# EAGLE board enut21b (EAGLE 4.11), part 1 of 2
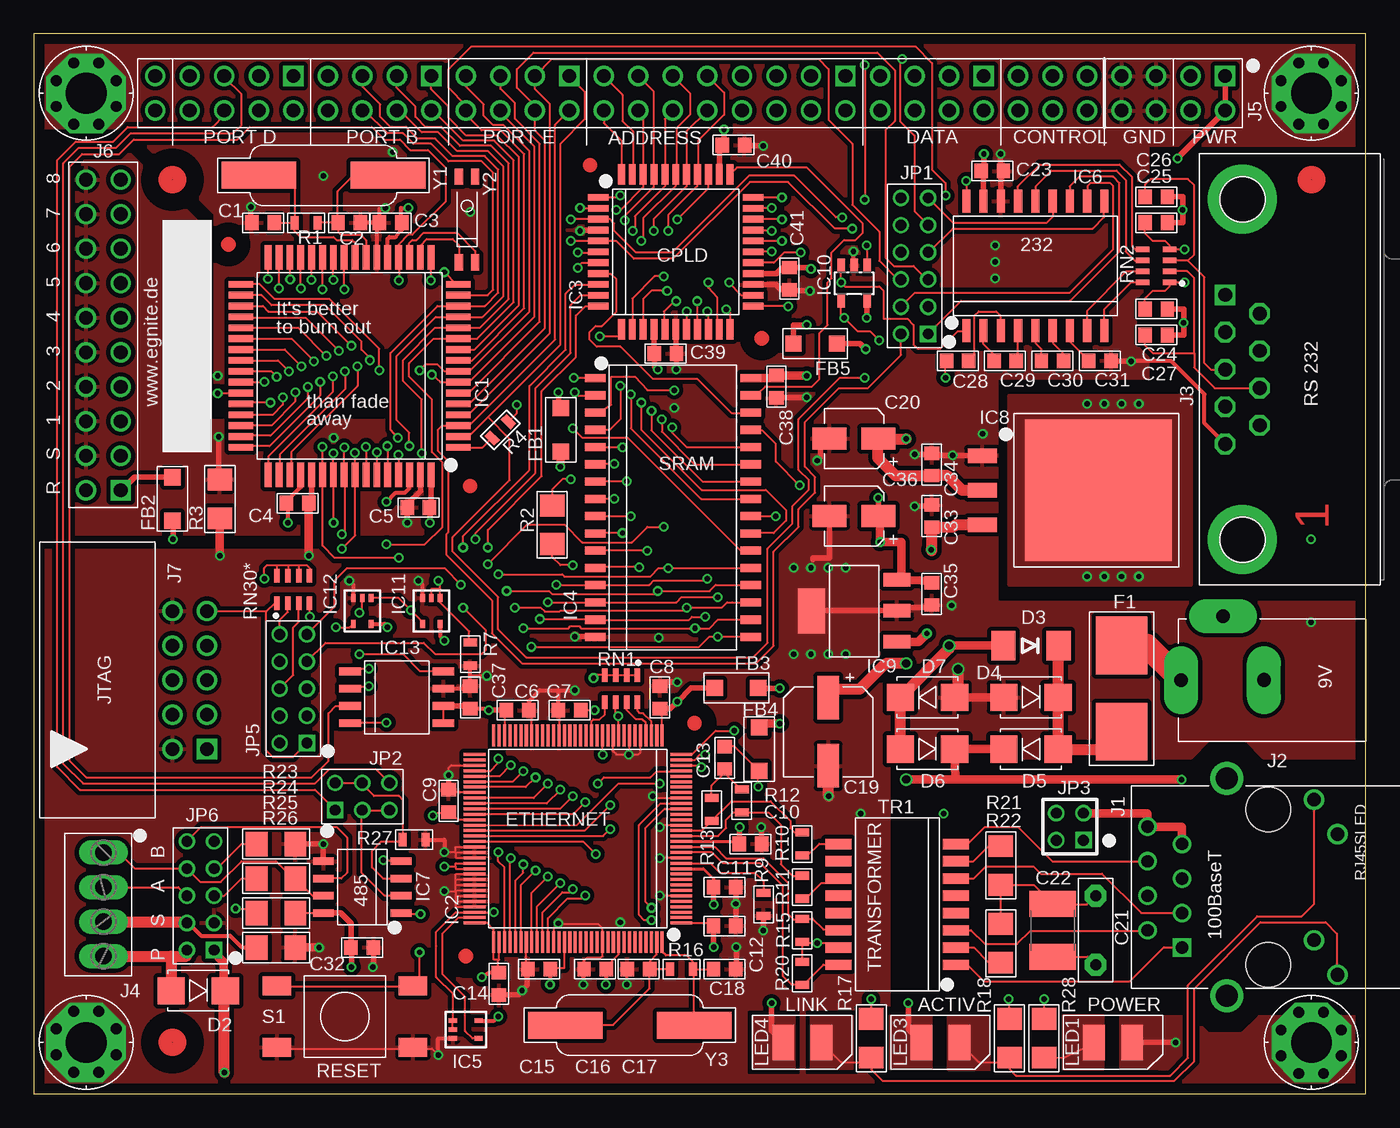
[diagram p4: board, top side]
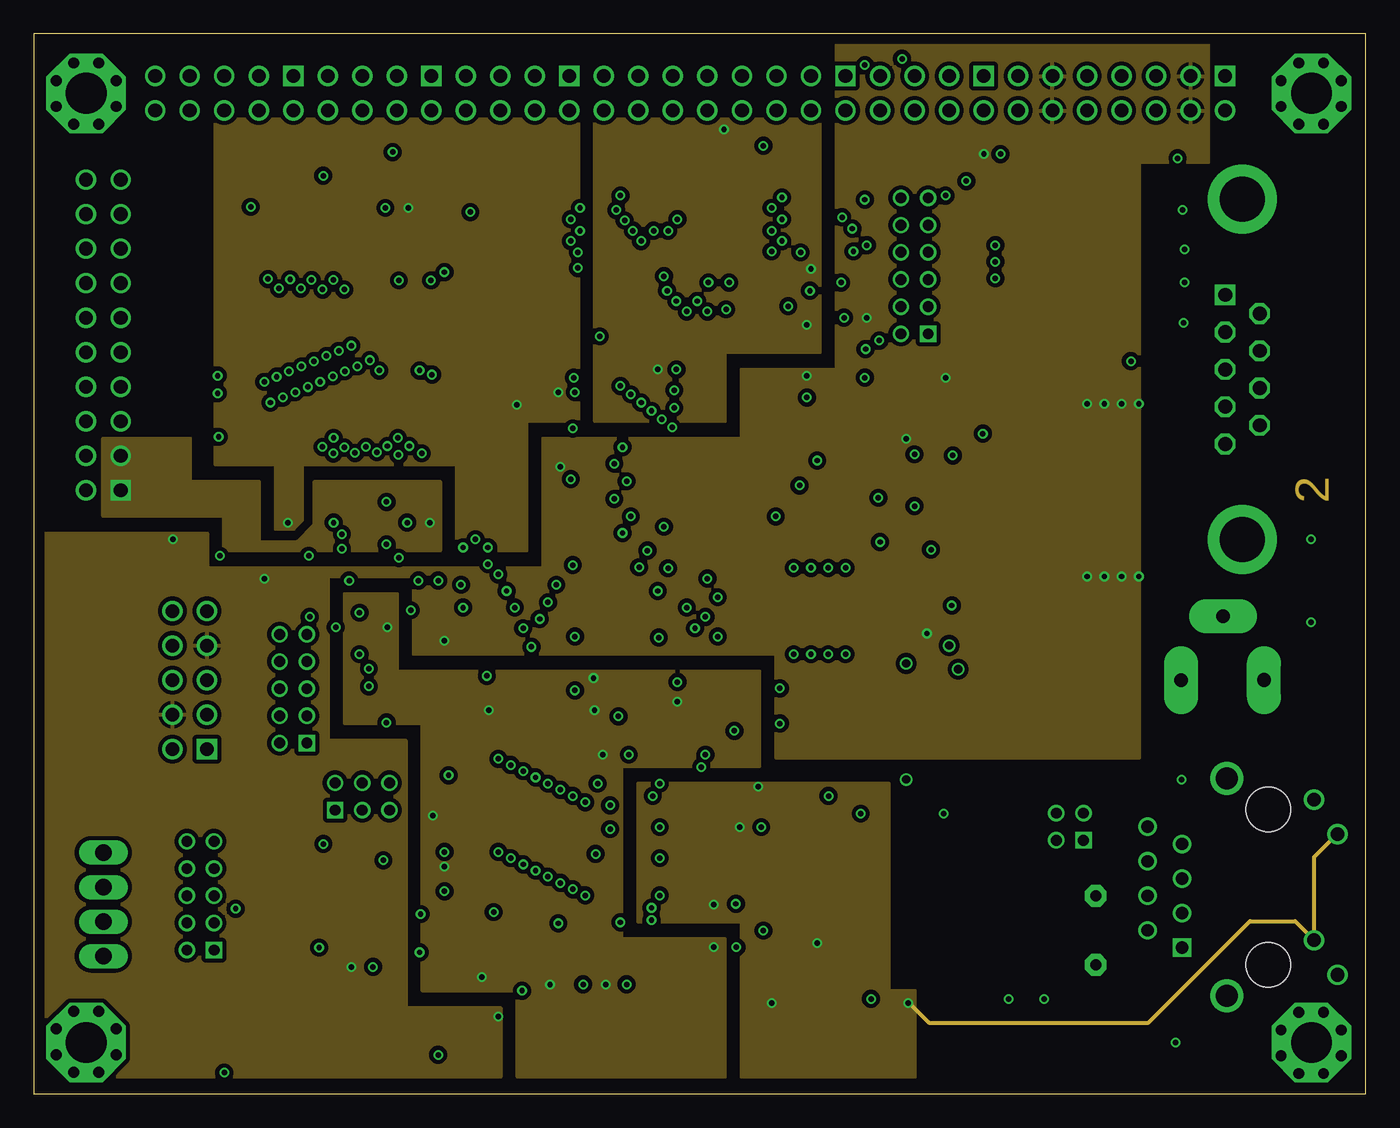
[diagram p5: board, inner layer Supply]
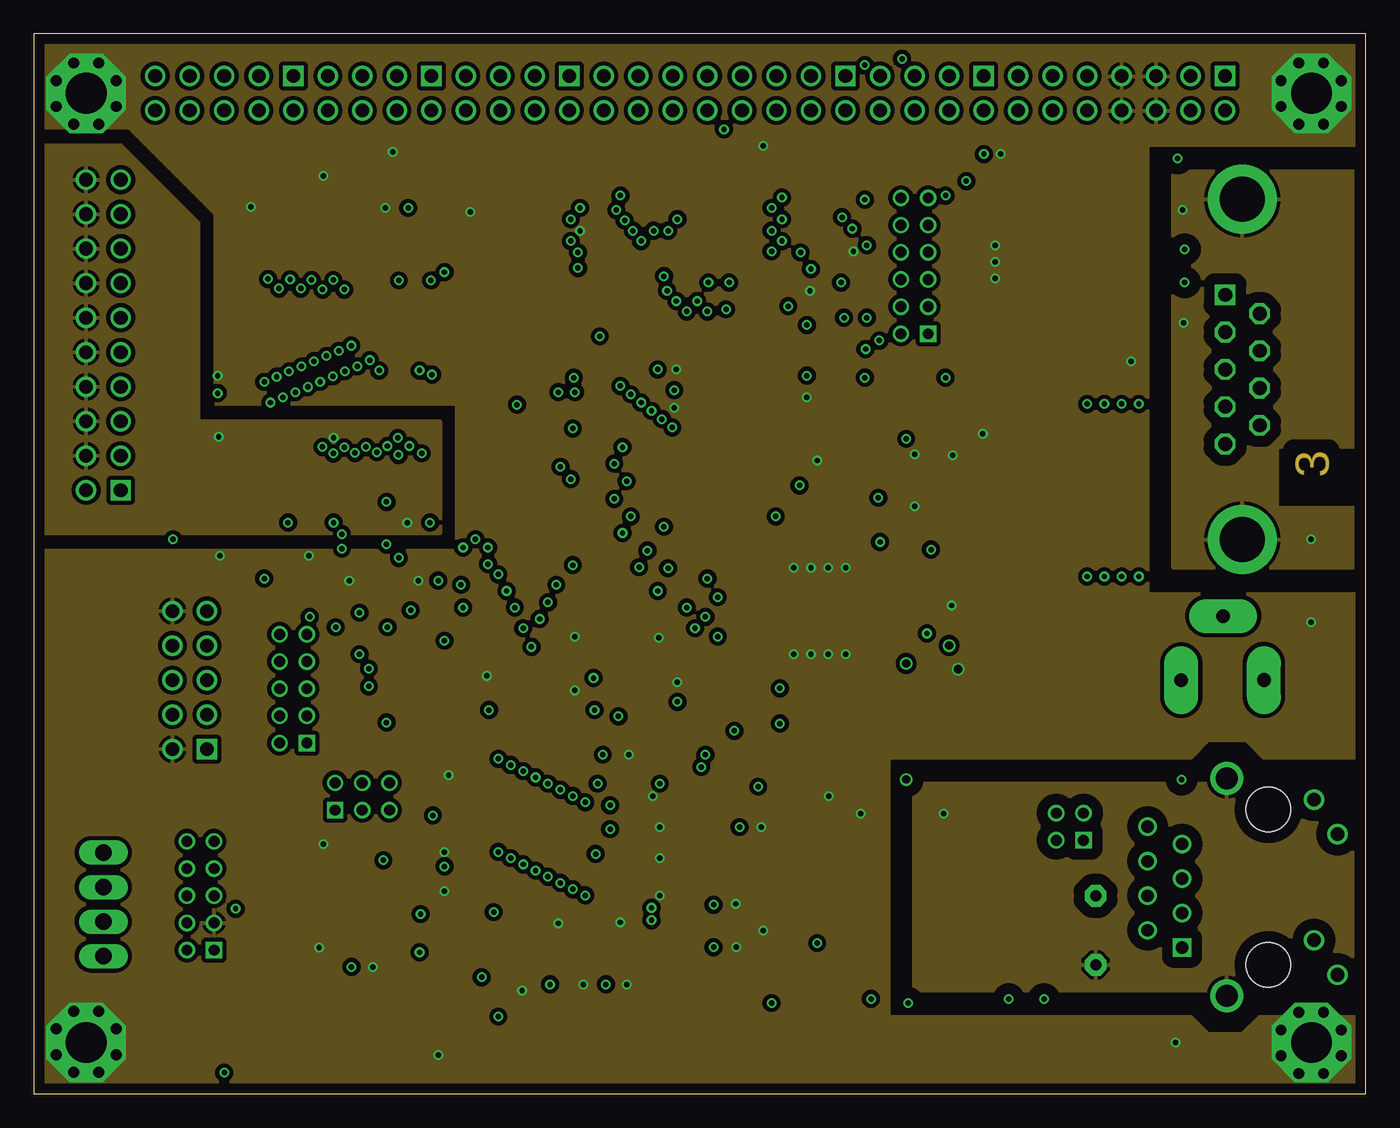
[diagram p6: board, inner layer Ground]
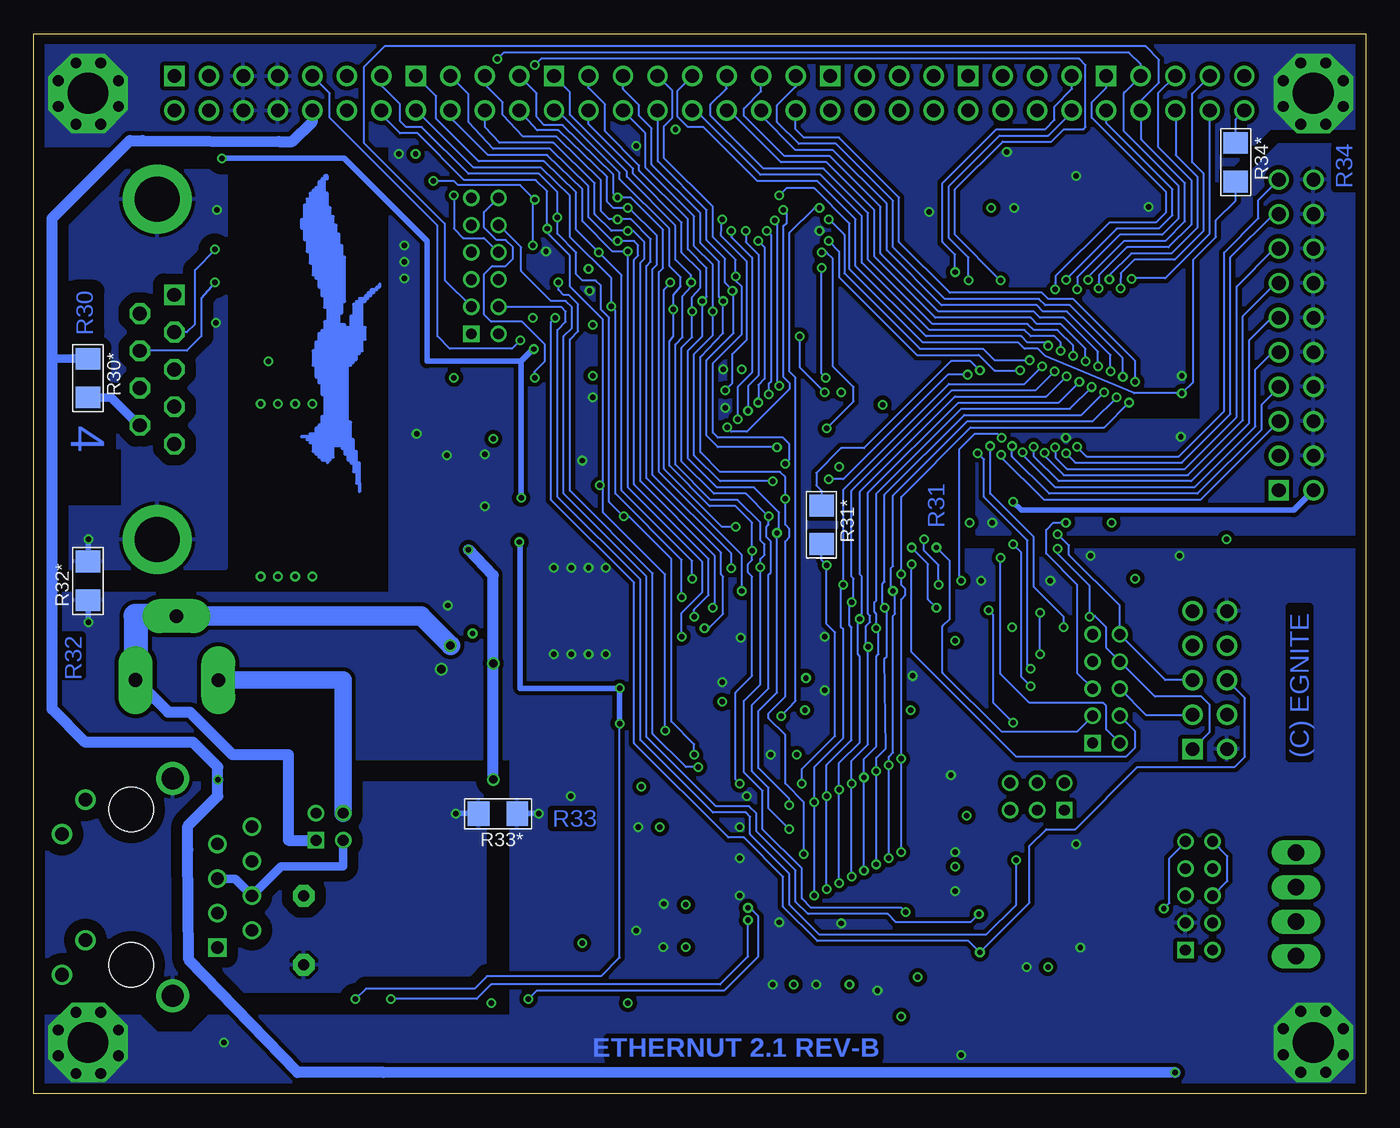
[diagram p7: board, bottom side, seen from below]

Size 97.99 x 78 mm. Coordinates in mm from the lower left corner, seen from the top.
Outline: 0,0 97.99,0 97.99,78 0,78 0,0
Copper layers (1*2+15*16): Top 0.035mm / dielectric 0.5mm / Supply 0.035mm / dielectric 0.5mm / Ground 0.035mm / dielectric 0.5mm / Bottom 0.035mm
Design rules "default": minimum track width 6mil, minimum drill 0.4mm, track to track 7mil, track to pad 7mil, pad to pad 7mil, via to via 7mil, smd to smd 7mil, copper to edge 30mil, drill to drill 15mil, minimum pad ring 8mil, minimum via ring 6mil, stop-mask expansion 0mil, vias tented up to drill 4mm, thermal gap 10mil
Net classes: 1 Supply1A: width 0.61 mm; 4 Ground: width 0.406 mm

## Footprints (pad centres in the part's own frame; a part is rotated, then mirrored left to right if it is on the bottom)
C0603 = smd 0.991 x 1.092: 1 -0.824,0; 2 0.824,0
ALUC6.3 = smd 3.2 x 1.6: + -2.5,0; - 2.5,0
ALUC4.0 = smd 2.5 x 1.6: + -1.8,0; - 1.8,0
C5.0 = drill 0.813 pad 1.6 octagon: 1 -2.54,0; 2 2.54,0
RCL_C1812 = smd 1.9 x 3.4: 1 -1.95,0; 2 1.95,0
SMA = smd 2 x 2: A 2,0; C -2,0
SMB = smd 1.778 x 2.159: A 2.032,0; C -2.032,0
OMNI-BLOK = smd 4.242 x 3.81: 1 -3.175,0; 2 3.175,0
BLM31 = smd 1.2 x 1.2: 1 -1.6,0; 2 1.6,0
MOUNT3 = drill 3 pad 5.842 octagon: B3,0 0,0
TQFP64 = smd 0.5 x 1.8: 1 -6,-8; 2 -5.2,-8; 3 -4.4,-8; 4 -3.6,-8; 5 -2.8,-8; 6 -2,-8; 7 -1.2,-8; 8 -0.4,-8; 9 0.4,-8; 10 1.2,-8; 11 2,-8; 12 2.8,-8; 13 3.6,-8; 14 4.4,-8; 15 5.2,-8; 16 6,-8; 33 6,8; 34 5.2,8; 35 4.4,8; 36 3.6,8; 37 2.8,8; 38 2,8; 39 1.2,8; 40 0.4,8; 41 -0.4,8; 42 -1.2,8; 43 -2,8; 44 -2.8,8; 45 -3.6,8; 46 -4.4,8; 47 -5.2,8; 48 -6,8 | smd 1.8 x 0.5: 17 8,-6; 18 8,-5.2; 19 8,-4.4; 20 8,-3.6; 21 8,-2.8; 22 8,-2; 23 8,-1.2; 24 8,-0.4; 25 8,0.4; 26 8,1.2; 27 8,2; 28 8,2.8; 29 8,3.6; 30 8,4.4; 31 8,5.2; 32 8,6; 49 -8,6; 50 -8,5.2; 51 -8,4.4; 52 -8,3.6; 53 -8,2.8; 54 -8,2; 55 -8,1.2; 56 -8,0.4; 57 -8,-0.4; 58 -8,-1.2; 59 -8,-2; 60 -8,-2.8; 61 -8,-3.6; 62 -8,-4.4; 63 -8,-5.2; 64 -8,-6
TQFP128 = smd 0.222 x 1.6: 1 -6.2,-7.6; 2 -5.8,-7.6; 3 -5.4,-7.6; 4 -5,-7.6; 5 -4.6,-7.6; 6 -4.2,-7.6; 7 -3.8,-7.6; 8 -3.4,-7.6; 9 -3,-7.6; 10 -2.6,-7.6; 11 -2.2,-7.6; 12 -1.8,-7.6; 13 -1.4,-7.6; 14 -1,-7.6; 15 -0.6,-7.6; 16 -0.2,-7.6; 17 0.2,-7.6; 18 0.6,-7.6; 19 1,-7.6; 20 1.4,-7.6; 21 1.8,-7.6; 22 2.2,-7.6; 23 2.6,-7.6; 24 3,-7.6; 25 3.4,-7.6; 26 3.8,-7.6; 27 4.2,-7.6; 28 4.6,-7.6; 29 5,-7.6; 30 5.4,-7.6; 31 5.8,-7.6; 32 6.2,-7.6; 65 6.2,7.6; 66 5.8,7.6; 67 5.4,7.6; 68 5,7.6; 69 4.6,7.6; 70 4.2,7.6; 71 3.8,7.6; 72 3.4,7.6; 73 3,7.6; 74 2.6,7.6; 75 2.2,7.6; 76 1.8,7.6; 77 1.4,7.6; 78 1,7.6; 79 0.6,7.6; 80 0.2,7.6; 81 -0.2,7.6; 82 -0.6,7.6; 83 -1,7.6; 84 -1.4,7.6; 85 -1.8,7.6; 86 -2.2,7.6; 87 -2.6,7.6; 88 -3,7.6; 89 -3.4,7.6; 90 -3.8,7.6; 91 -4.2,7.6; 92 -4.6,7.6; 93 -5,7.6; 94 -5.4,7.6; 95 -5.8,7.6; 96 -6.2,7.6 | smd 1.6 x 0.222: 33 7.6,-6.2; 34 7.6,-5.8; 35 7.6,-5.4; 36 7.6,-5; 37 7.6,-4.6; 38 7.6,-4.2; 39 7.6,-3.8; 40 7.6,-3.4; 41 7.6,-3; 42 7.6,-2.6; 43 7.6,-2.2; 44 7.6,-1.8; 45 7.6,-1.4; 46 7.6,-1; 47 7.6,-0.6; 48 7.6,-0.2; 49 7.6,0.2; 50 7.6,0.6; 51 7.6,1; 52 7.6,1.4; 53 7.6,1.8; 54 7.6,2.2; 55 7.6,2.6; 56 7.6,3; 57 7.6,3.4; 58 7.6,3.8; 59 7.6,4.2; 60 7.6,4.6; 61 7.6,5; 62 7.6,5.4; 63 7.6,5.8; 64 7.6,6.2; 97 -7.6,6.2; 98 -7.6,5.8; 99 -7.6,5.4; 100 -7.6,5; 101 -7.6,4.6; 102 -7.6,4.2; 103 -7.6,3.8; 104 -7.6,3.4; 105 -7.6,3; 106 -7.6,2.6; 107 -7.6,2.2; 108 -7.6,1.8; 109 -7.6,1.4; 110 -7.6,1; 111 -7.6,0.6; 112 -7.6,0.2; 113 -7.6,-0.2; 114 -7.6,-0.6; 115 -7.6,-1; 116 -7.6,-1.4; 117 -7.6,-1.8; 118 -7.6,-2.2; 119 -7.6,-2.6; 120 -7.6,-3; 121 -7.6,-3.4; 122 -7.6,-3.8; 123 -7.6,-4.2; 124 -7.6,-4.6; 125 -7.6,-5; 126 -7.6,-5.4; 127 -7.6,-5.8; 128 -7.6,-6.2
VQFP44 = smd 0.5 x 1.5: 1 -4,-5.7; 2 -3.2,-5.7; 3 -2.4,-5.7; 4 -1.6,-5.7; 5 -0.8,-5.7; 6 0,-5.7; 7 0.8,-5.7; 8 1.6,-5.7; 9 2.4,-5.7; 10 3.2,-5.7; 11 4,-5.7; 23 4,5.7; 24 3.2,5.7; 25 2.4,5.7; 26 1.6,5.7; 27 0.8,5.7; 28 0,5.7; 29 -0.8,5.7; 30 -1.6,5.7; 31 -2.4,5.7; 32 -3.2,5.7; 33 -4,5.7 | smd 1.5 x 0.5: 12 5.7,-4; 13 5.7,-3.2; 14 5.7,-2.4; 15 5.7,-1.6; 16 5.7,-0.8; 17 5.7,0; 18 5.7,0.8; 19 5.7,1.6; 20 5.7,2.4; 21 5.7,3.2; 22 5.7,4; 34 -5.7,4; 35 -5.7,3.2; 36 -5.7,2.4; 37 -5.7,1.6; 38 -5.7,0.8; 39 -5.7,0; 40 -5.7,-0.8; 41 -5.7,-1.6; 42 -5.7,-2.4; 43 -5.7,-3.2; 44 -5.7,-4
TSOP2-32 = smd 0.6 x 1.5: 1 -9.525,-5.715; 2 -8.255,-5.715; 3 -6.985,-5.715; 4 -5.715,-5.715; 5 -4.445,-5.715; 6 -3.175,-5.715; 7 -1.905,-5.715; 8 -0.635,-5.715; 9 0.635,-5.715; 10 1.905,-5.715; 11 3.175,-5.715; 12 4.445,-5.715; 13 5.715,-5.715; 14 6.985,-5.715; 15 8.255,-5.715; 16 9.525,-5.715; 17 9.525,5.715; 18 8.255,5.715; 19 6.985,5.715; 20 5.715,5.715; 21 4.445,5.715; 22 3.175,5.715; 23 1.905,5.715; 24 0.635,5.715; 25 -0.635,5.715; 26 -1.905,5.715; 27 -3.175,5.715; 28 -4.445,5.715; 29 -5.715,5.715; 30 -6.985,5.715; 31 -8.255,5.715; 32 -9.525,5.715
SOT353 = smd 0.35 x 0.6: 1 -0.65,-0.95; 2 0,-0.95; 3 0.65,-0.95; 4 0.65,0.95; 5 -0.65,0.95
SO18W = smd 0.6 x 1.7: 1 -5.08,-4.763; 2 -3.81,-4.763; 3 -2.54,-4.763; 4 -1.27,-4.763; 5 0,-4.763; 6 1.27,-4.763; 7 2.54,-4.763; 8 3.81,-4.763; 9 5.08,-4.763; 10 5.08,4.763; 11 3.81,4.763; 12 2.54,4.763; 13 1.27,4.763; 14 0,4.763; 15 -1.27,4.763; 16 -2.54,4.763; 17 -3.81,4.763; 18 -5.08,4.763
SOIC8 = smd 0.559 x 1.524: 1 -1.905,-2.857; 2 -0.635,-2.857; 3 0.635,-2.857; 4 1.905,-2.857; 5 1.905,2.857; 6 0.635,2.857; 7 -0.635,2.857; 8 -1.905,2.857
DDPAK-ST = smd 1.07 x 2.16: 1 -2.54,-6.438; 2 0,-6.438; 3 2.54,-6.438 | smd 10.4 x 10.8: 4 0,2.1
SOT-223 = smd 1 x 2: 1 -2.261,-3.15; 2 0.025,-3.15; 3 2.311,-3.15 | smd 3.3 x 2: 4 0,3.15
SOT23-5L = smd 0.55 x 0.99: 1 -0.95,-1.3; 2 0,-1.3; 3 0.95,-1.3; 4 0.95,1.3; 5 -0.95,1.3
SOIC-8-209 = smd 0.58 x 1.6: 1 -1.905,-3.429; 2 -0.635,-3.429; 3 0.635,-3.429; 4 1.905,-3.429; 5 1.905,3.429; 6 0.635,3.429; 7 -0.635,3.429; 8 -1.905,3.429
RJ45S = drill 0.9 square: 1 4.445,-6.35 | drill 0.9 round: 2 3.175,-8.89; 3 1.905,-6.35; 4 0.635,-8.89; 5 -0.635,-6.35; 6 -1.905,-8.89; 7 -3.175,-6.35; 8 -4.445,-8.89 | drill 1 round: D1+ 6.452,5.08; D1- 3.912,3.378; D2+ -6.452,3.378; D2- -3.912,5.08 | drill 1.63 round: S1 8.001,-3.048; S2 -8.001,-3.048 | hole 3.3: 5.715,0; -5.715,0
DC2.1 = drill 1.016 pad 2.5 long: 1 -6.1,-0.01; 2 0,0; 3 -3.01,4.7
SUBD9F = drill 1.016 pad 1.524 square: 1 -5.486,-5.08 | drill 1.016 pad 1.524 octagon: 2 -2.743,-5.08; 3 0,-5.08; 4 2.743,-5.08; 5 5.486,-5.08; 6 -4.115,-2.54; 7 -1.372,-2.54; 8 1.372,-2.54; 9 4.115,-2.54 | drill 3.302 pad 5.08 round: G1 -12.522,-3.81; G2 12.522,-3.81
MINISK = drill 1.2 long: 1 -3.81,0; 2 -1.27,0; 3 1.27,0; 4 3.81,0
NUTEXP = drill 1 square: 1 39.37,1.27; 15 21.59,1.27; 23 11.43,1.27; 39 -8.89,1.27; 47 -19.05,1.27; 55 -29.21,1.27 | drill 1 round: 2 39.37,-1.27; 3 36.83,1.27; 4 36.83,-1.27; 5 34.29,1.27; 6 34.29,-1.27; 7 31.75,1.27; 8 31.75,-1.27; 9 29.21,1.27; 10 29.21,-1.27; 11 26.67,1.27; 12 26.67,-1.27; 13 24.13,1.27; 14 24.13,-1.27; 16 21.59,-1.27; 17 19.05,1.27; 18 19.05,-1.27; 19 16.51,1.27; 20 16.51,-1.27; 21 13.97,1.27; 22 13.97,-1.27; 24 11.43,-1.27; 25 8.89,1.27; 26 8.89,-1.27; 27 6.35,1.27; 28 6.35,-1.27; 29 3.81,1.27; 30 3.81,-1.27; 31 1.27,1.27; 32 1.27,-1.27; 33 -1.27,1.27; 34 -1.27,-1.27; 35 -3.81,1.27; 36 -3.81,-1.27; 37 -6.35,1.27; 38 -6.35,-1.27; 40 -8.89,-1.27; 41 -11.43,1.27; 42 -11.43,-1.27; 43 -13.97,1.27; 44 -13.97,-1.27; 45 -16.51,1.27; 46 -16.51,-1.27; 48 -19.05,-1.27; 49 -21.59,1.27; 50 -21.59,-1.27; 51 -24.13,1.27; 52 -24.13,-1.27; 53 -26.67,1.27; 54 -26.67,-1.27; 56 -29.21,-1.27; 57 -31.75,1.27; 58 -31.75,-1.27; 59 -34.29,1.27; 60 -34.29,-1.27; 61 -36.83,1.27; 62 -36.83,-1.27; 63 -39.37,1.27; 64 -39.37,-1.27
SLLP2X10 = drill 1 square: 1 -11.43,-1.27 | drill 1 round: 2 -11.43,1.27; 3 -8.89,-1.27; 4 -8.89,1.27; 5 -6.35,-1.27; 6 -6.35,1.27; 7 -3.81,-1.27; 8 -3.81,1.27; 9 -1.27,-1.27; 10 -1.27,1.27; 11 1.27,-1.27; 12 1.27,1.27; 13 3.81,-1.27; 14 3.81,1.27; 15 6.35,-1.27; 16 6.35,1.27; 17 8.89,-1.27; 18 8.89,1.27; 19 11.43,-1.27; 20 11.43,1.27
ML10A = drill 1 pad 1.422 square: 1 -5.08,-6.35 | drill 1 pad 1.422 round: 2 -5.08,-3.81; 3 -2.54,-6.35; 4 -2.54,-3.81; 5 0,-6.35; 6 0,-3.81; 7 2.54,-6.35; 8 2.54,-3.81; 9 5.08,-6.35; 10 5.08,-3.81
SLY2X6 = drill 0.8 square: 1 -5,-1 | drill 0.8 round: 2 -5,1; 3 -3,-1; 4 -3,1; 5 -1,-1; 6 -1,1; 7 1,-1; 8 1,1; 9 3,-1; 10 3,1; 11 5,-1; 12 5,1
SLY2X3 = drill 0.8 square: 1 -2,-1 | drill 0.8 round: 2 -2,1; 3 0,-1; 4 0,1; 5 2,-1; 6 2,1
SLY2X2 = drill 0.8 square: 1 -1,-1 | drill 0.8 round: 2 -1,1; 3 1,-1; 4 1,1
SLY2X5 = drill 0.8 square: 1 -4,-1 | drill 0.8 round: 2 -4,1; 3 -2,-1; 4 -2,1; 5 0,-1; 6 0,1; 7 2,-1; 8 2,1; 9 4,-1; 10 4,1
P-LCC-2 = smd 1.6 x 2.6: A 1.4,0; C -1.4,0
R0603 = smd 0.6 x 1: 1 -0.85,0; 2 0.85,0
R1206 = smd 1.6 x 1.803: 1 -1.422,0; 2 1.422,0
CAY16 = smd 0.4 x 1: 1 -1.2,-1; 2 -0.4,-1; 3 0.4,-1; 4 1.2,-1; 5 1.2,1; 6 0.4,1; 7 -0.4,1; 8 -1.2,1
LSH = smd 2.1 x 1.4: 1 -5,-2.25; 2 5,-2.25; 3 -5,2.25; 4 5,2.25
SOIC16-12TR = smd 0.762 x 1.905: 1 -4.445,-4.318; 2 -3.175,-4.318; 3 -1.905,-4.318; 4 -0.635,-4.318; 5 0.635,-4.318; 6 1.905,-4.318; 7 3.175,-4.318; 8 4.445,-4.318; 9 4.445,4.318; 10 3.175,4.318; 11 1.905,4.318; 12 0.635,4.318; 13 -0.635,4.318; 14 -1.905,4.318; 15 -3.175,4.318; 16 -4.445,4.318
HC49SM = smd 5.5 x 2: P$1 4.75,0; P$2 -4.75,0
MC-146 = smd 1.2 x 0.6: 1 -3.15,-0.6; 2 3.15,-0.6; 3 3.15,0.6; 4 -3.15,0.6

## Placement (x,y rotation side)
C1  22p  [C0603]  16.86,64.11 180 top
C2  22p  [C0603]  23.21,64.11 0 top
C3  100n  [C0603]  26.24,64.11 180 top
C4  100n  [C0603]  19.4,43.47 0 top
C5  100n  [C0603]  28.29,43.15 180 top
C6  100n  [C0603]  35.59,28.23 0 top
C7  100n  [C0603]  39.4,28.23 180 top
C8  100n  [C0603]  46.07,29.18 90 top
C9  100n  [C0603]  30.51,21.56 90 top
C10  100n  [C0603]  52.73,18.38 0 top
C11  100n  [C0603]  50.83,15.21 0 top
C12  100n  [C0603]  50.83,12.35 0 top
C13  10n  [C0603]  50.83,24.73 270 top
C14  100n  [C0603]  34.21,8.11 270 top
C15  100n  [C0603]  37.18,9.18 180 top
C16  100n  [C0603]  41.3,9.18 180 top
C17  22p  [C0603]  44.48,9.18 180 top
C18  22p  [C0603]  50.83,9.18 0 top
C19  100u 25V  [ALUC6.3]  58.45,26.64 270 top
C20  10u 16V  [ALUC4.0]  60.36,48.23 180 top
C21  1n 2kV  [C5.0]  78.14,12.04 270 top
C22  1n 1kV  [RCL_C1812]  74.96,12.04 270 top
C23  100n  [C0603]  70.52,67.91 0 top
C24  220p  [C0603]  82.58,57.75 0 top
C25  220p  [C0603]  82.58,64.11 0 top
C26  220p  [C0603]  82.58,66.01 0 top
C27  220p  [C0603]  82.58,55.85 0 top
C28  100n  [C0603]  67.97,53.95 0 top
C29  100n  [C0603]  71.47,53.95 0 top
C30  100n  [C0603]  74.96,53.95 0 top
C31  100n  [C0603]  78.45,53.95 180 top
C32  100n  [C0603]  24.16,10.77 0 top
C33  100n  [C0603]  66.07,42.52 90 top
C34  100n  [C0603]  66.07,46.32 90 top
C35  100n  [C0603]  66.07,36.8 270 top
C36  10u 16V  [ALUC4.0]  60.36,42.52 180 top
C37  100n  [C0603]  32.1,29.18 90 top
C38  100n  [C0603]  54.64,52.04 270 top
C39  100n  [C0603]  46.46,54.47 0 top
C40  100n  [C0603]  51.46,69.82 0 top
C41  100n  [C0603]  55.59,59.98 270 top
D2  S1A  [SMA]  12.09,7.59 180 top
D3  SM6T15CA  [SMB]  73.37,32.99 180 top
D4  S1A  [SMA]  73.37,25.37 0 top
D5  S1A  [SMA]  73.37,29.18 180 top
D6  S1A  [SMA]  65.75,25.37 180 top
D7  S1A  [SMA]  65.75,29.18 0 top
F1  1A  [OMNI-BLOK]  80.04,29.81 270 top
FB1  BLM31A601  [BLM31]  38.77,48.87 90 top
FB2  BLM31A601  [BLM31]  10.19,43.78 90 top
FB3  BLM31A601  [BLM31]  51.7,29.87 180 top
FB4  BLM31A601  [BLM31]  53.37,25.37 90 top
FB5  BLM31A601  [BLM31]  57.5,55.22 0 top
H1  [MOUNT3]  3.84,73.63 0 top
H2  [MOUNT3]  3.84,3.78 0 top
H3  [MOUNT3]  94.01,73.63 0 top
H4  [MOUNT3]  94.01,3.78 0 top
IC1  ATMEGA128-AC  [TQFP64]  23.23,53.57 90 top
IC2  LAN91C111-NE  [TQFP128]  40.03,18.77 90 top
IC3  XC9536XLVQ44  [VQFP44]  47.23,61.97 270 top
IC4  K6T4008C1C-VB70  [TSOP2-32]  47.02,43.15 270 top
IC5  74HC1G00GW  [SOT353]  31.78,4.73 270 top
IC6  MAX3222ECWN  [SO18W]  73.69,60.93 0 top
IC7  SP483ECN  [SOIC8]  24.16,15.21 90 top
IC8  LM1086IS  [DDPAK-ST]  76.23,44.42 270 top
IC9  LM3940IMP  [SOT-223]  60.36,35.53 90 top
IC10  MIC2775-46BM5  [SOT23-5L]  60.36,59.66 180 top
IC11  74HC1G00GW  [SOT353]  29.24,35.53 180 top
IC12  74LVC1G125GW  [SOT353]  24.16,35.53 180 top
IC13  AT45DB041B  [SOIC-8-209]  26.7,29.18 270 top
J1  RJ45SLED  [RJ45S]  90.84,15.21 270 top
J2  [DC2.1]  90.52,30.45 0 top
J3  [SUBD9F]  92.74,53.31 270 top
J4  [MINISK]  5.11,13.94 270 top
J5  [NUTEXP]  48.29,73.63 0 top
J6  [SLLP2X10]  5.11,55.85 90 top
J7  [ML10A]  6.38,30.45 90 top
JP1  [SLY2X6]  64.8,60.93 90 top
JP2  [SLY2X3]  24.16,21.88 0 top
JP3  [SLY2X2]  76.23,19.65 90 top
JP5  JP2X5  [SLY2X5]  19.08,29.81 90 top
JP6  [SLY2X5]  12.25,14.58 90 top
LED1  [P-LCC-2]  79.41,3.78 180 top
LED3  [P-LCC-2]  66.7,3.78 180 top
LED4  [P-LCC-2]  56.55,3.78 180 top
LOGO  [LOGO]  72.55,44.29 90 bottom
R1  1M  [R0603]  20.03,64.11 0 top
R2  0  [R1206]  38.13,41.88 270 top
R3  0  [R1206]  13.68,43.78 90 top
R4  12k  [R0603]  34.32,48.87 45 top
R7  12k  [R0603]  32.1,32.35 90 top
R9  12k  [R0603]  53.69,13.94 90 top
R10  24.9  [R0603]  56.55,18.38 270 top
R11  24.9  [R0603]  56.55,15.21 270 top
R12  24.9  [R0603]  52.1,21.56 90 top
R13  24.9  [R0603]  49.88,20.92 90 top
R15  49.9  [R0603]  56.55,12.04 270 top
R16  1M  [R0603]  47.66,9.18 180 top
R17  560  [R1206]  61.62,4.1 270 top
R18  560  [R1206]  71.78,4.1 270 top
R20  49.9  [R0603]  56.55,8.86 90 top
R21  75  [R1206]  71.15,16.8 90 top
R22  75  [R1206]  71.15,11.08 270 top
R23  560  [R1206]  17.81,18.38 180 top
R24  120  [R1206]  17.81,15.85 180 top
R25  560  [R1206]  17.81,13.31 0 top
R26  120  [R1206]  17.81,10.77 0 top
R27  12k  [R0603]  27.97,18.7 180 top
R28  560  [R1206]  74.33,4.1 90 top
R30*  0  [R1206]  94.01,52.67 270 bottom
R31*  0  [R1206]  40.04,41.88 270 bottom
R32*  0  [R1206]  94.01,37.75 90 bottom
R33*  0  [R1206]  63.85,20.61 180 bottom
R34*  0  [R1206]  9.55,68.55 270 bottom
RN1  10k  [CAY16]  43.21,29.81 180 top
RN2  22  [CAY16]  82.58,60.93 90 top
RN30*  10k  [CAY16]  19.08,37.12 0 top
S1  LSH  [LSH]  22.89,5.68 180 top
TR1  TG110-S050N2  [SOIC16-12TR]  63.53,13.94 90 top
U$9  [MARK1]  32.1,44.74 0 top
U$10  [MARK1]  14.32,62.52 0 top
U$11  [MARK1]  31.78,10.13 0 top
U$12  [MARK1]  48.61,27.27 0 top
U$13  [MARK1]  40.92,68.35 0 top
U$14  [MARK1]  53.55,55.59 0 top
U$15  [MARK2]  10.19,67.28 0 top
U$16  [MARK2]  94.01,67.28 0 top
U$17  [MARK2]  10.19,3.78 0 top
Y1  14.7456 MHz  [HC49SM]  21.3,67.6 180 top
Y2  32.768 kHz  [MC-146]  31.87,64.35 90 top
Y3  25 MHz  [HC49SM]  43.84,5.05 0 top

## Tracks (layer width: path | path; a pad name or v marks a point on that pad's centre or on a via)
A0  (via drill 0.4)
  Top 0.152: IC2.94 32.41,13.38 | IC2.94 | IC4.12 41.33,38.76 v44.53,38.76 | IC3.21 50.47,56.27 50.25,56.42 50.25,58.64 49.64,59.33 v49.64,59.71 | IC2.94 v33.83,13.37 | v33.83,13.37 | 31.03,13.37 IC2.94 | 31.03,13.37 | 29.6,10.87 29.6,8.58 30.83,7.35 IC5.1 30.82,5.38 30.82,4.73 IC5.2 | 29.6,10.87 | 31.03,13.37 29.6,11.94 29.6,10.87
  Bottom 0.152: J5.23 58.55,73.73 58.55,72.05 54.36,67.86 54.36,67.48 50.78,63.9 50.78,61.39 49.64,60.24 v49.64,59.71 49.64,59.41 50.25,58.72 50.25,55.67 50.78,55.14 50.78,46.3 48.19,43.71 46.21,43.71 44.53,42.03 44.53,40.74 44.23,40.43 44.23,39.67 44.53,39.37 v44.53,38.76 44.53,30.14 45.75,28.93 45.75,23.67 44.38,22.3 44.38,19.48 41.48,16.58 41.48,14.37 40.8,13.69 34.17,13.69 33.85,13.37 v33.83,13.37
A0\
  Top 0.152: 31.23,12.97 IC2.95 | 31.23,12.97 | 30.05,10.64 30.05,8.81 31.73,7.13 31.73,4.62 32.27,4.08 IC5.4 | 30.05,10.64 30.05,10.65 | 31.23,12.97 30.05,11.79 30.05,10.64
A1  (via drill 0.4)
  Top 0.152: IC2.78 | IC2.78 32.43,19.78 | IC4.11 | v45.14,39.98 IC4.11 | IC2.78 39.96,19.78 43.01,22.83 v46.05,22.83 | IC3.22 51.24,57.5 v50.93,57.73
  Bottom 0.152: J5.24 59.47,72.36 54.89,67.79 54.89,67.33 51.24,63.67 51.24,60.93 50.4,60.09 50.4,59.41 50.93,58.8 v50.93,57.73 50.93,55.75 51.24,55.37 51.24,46.22 48.27,43.25 46.36,43.25 45.14,42.03 v45.14,39.98 45.14,39.29 45.45,38.98 45.45,38.38 45.14,38.07 45.14,30.75 46.36,29.54 46.36,23.13 v46.05,22.83
A2  (via drill 0.4)
  Top 0.152: IC4.10 41.33,41.27 v43.31,41.27 | IC3.19 48.8,56.27 v48.8,58.34 | IC2.79 40.54,19.37 v42.4,21.23
  Bottom 0.152: J5.25 57.18,74.04 55.96,72.82 55.96,70.84 53.45,68.32 53.45,67.94 49.87,64.36 49.87,62.15 48.49,60.78 48.49,58.64 v48.8,58.34 48.8,55.75 49.87,54.68 49.87,46.76 47.73,44.62 44.99,44.62 43.16,42.79 43.16,41.42 v43.31,41.27 43.31,29.54 44.68,28.16 44.68,23.97 42.4,21.69 v42.4,21.23
A3  (via drill 0.4)
  Top 0.152: IC2.80 | IC4.9 41.33,42.49 v43.92,42.49 | IC3.20 v49.56,57.58 | IC2.80 41.89,18.97 v42.4,19.48
  Bottom 0.152: v42.4,19.48 43.92,21 43.92,22.52 45.14,23.74 45.14,28.62 43.92,29.84 43.92,38.22 43.77,38.38 43.77,40.66 44.07,40.97 44.07,41.73 43.92,41.88 v43.92,42.49 45.6,44.17 47.96,44.17 50.32,46.53 50.32,54.91 49.56,55.67 v49.56,57.58 49.56,58.64 48.95,59.33 48.95,60.55 50.32,61.92 50.32,64.13 53.9,67.71 53.9,68.09 57.18,71.37 J5.26
A4  (via drill 0.4)
  Top 0.152: IC2.81 | IC2.81 | IC2.81 | IC4.8 | v42.7,43.78 IC4.8 | IC3.16 46.36,56.27 46.36,57.58 47.12,58.34 v47.27,58.34 | IC2.81 40.41,18.57 v41.33,17.65
  Bottom 0.152: J5.27 54.64,73.94 53.45,72.74 53.45,71.98 52.53,71.06 52.53,68.4 48.95,64.82 48.95,62.61 47.58,61.23 47.58,58.64 v47.27,58.34 47.27,55.98 48.95,54.22 48.95,47.21 47.5,45.77 43.08,45.77 42.7,45.38 v42.7,43.78 42.7,41.88 42.4,41.57 42.4,40.97 42.7,40.66 42.7,29.23 43.92,28.01 43.92,27.63 42.7,26.41 42.7,22.83 41.33,21.46 v41.33,17.65
A5  (via drill 0.4)
  Top 0.152: IC4.7 41.33,45.08 v43.62,45.08 | IC3.18 v48.04,57.58
  Bottom 0.152: v43.62,45.08 47.5,45.08 49.41,46.98 49.41,54.45 48.04,55.82 v48.04,57.58 48.04,61.01 49.41,62.38 49.41,64.59 52.99,68.17 52.99,70.68 54.64,72.33 J5.28
A6  (via drill 0.4)
  Top 0.152: 41.33,46.38 41.3,46.35 IC4.6 | 41.33,46.38 41.41,46.3 | 41.33,46.38 v42.7,46.38 | IC3.13 44.03,58.52 45.67,60.17 v46.36,60.17
  Bottom 0.152: J5.29 51.01,73.81 51.01,71.83 51.62,71.22 51.62,68.86 48.04,65.27 48.04,63.06 46.36,61.39 v46.36,60.17 46.36,59.86 45.9,59.41 45.9,55.9 48.04,53.77 48.04,48.66 47.66,48.28 42.85,48.28 42.4,47.82 42.4,46.68 v42.7,46.38
A7  (via drill 0.4)
  Top 0.152: 41.33,47.59 | IC4.5 41.33,47.59 | 41.33,47.59 v43.31,47.59 | v43.31,47.59 | IC3.14 44.83,58.49 45.45,59.1 v46.59,59.1
  Bottom 0.152: v43.31,47.59 47.66,47.59 48.49,48.43 48.49,54 46.51,55.98 46.51,59.02 v46.59,59.1 47.12,59.71 47.12,61.46 48.49,62.84 48.49,65.05 52.08,68.63 52.08,72.36 J5.30
A8  (via drill 0.4)
  Top 0.152: J5.31 50.78,73.68 50.78,72.05 48.87,70.15 48.87,67.71 IC3.37 | IC4.27 48.62,46.32 46.21,48.74 v46.21,49.65 | 48.8,67.48 48.83,67.52 IC3.37 | IC1.35 16.85,57.97 17.25,57.58 20.83,57.58 v23.35,55.06 | IC3.37 48.8,67.63 48.8,66.8 46.66,64.66 v46.66,63.52
  Bottom 0.152: v23.35,55.06 23.58,55.29 24.87,55.29 25.33,55.75 32.34,55.75 37.52,60.93 37.52,64.36 40.34,67.18 44.76,67.18 48.72,71.14 49.87,71.14 50.63,71.9 50.63,73.83 J5.31 | v46.21,49.65 46.21,52.02 45.14,53.08 45.14,61.54 46.66,63.06 v46.66,63.52
A9  (via drill 0.4)
  Top 0.152: 48.04,69.46 48.03,69.46 | J5.32 48.04,70.84 48.04,69.46 | IC4.26 49.2,45.05 45.45,48.81 v45.45,50.26 | IC3.38 48.04,69.46 | 48.04,67.41 48.03,67.41 IC3.38 | IC1.36 15.29,57.12 19.99,57.12 v22.43,54.68 | IC3.38 48.04,67.66 48.04,66.8 45.6,64.36 v45.6,63.52
  Bottom 0.152: v22.43,54.68 22.43,55.29 22.89,55.75 24.64,55.75 25.1,56.21 32.11,56.21 37.06,61.16 37.06,64.59 40.11,67.64 44.53,67.64 49.26,72.36 J5.32 | v45.45,50.26 45.45,52.09 44.68,52.85 44.68,61.77 45.6,62.68 v45.6,63.52
A10  (via drill 0.4)
  Top 0.152: J5.33 48.27,73.66 48.27,72.05 47.27,71.06 47.27,67.71 IC3.39 | v44.68,50.87 44.68,48.89 49.13,44.45 53.85,44.45 55.35,42.95 55.35,42.19 54.44,41.27 53.06,41.27 53.04,41.24 IC4.23 | 47.27,67.41 47.23,67.45 IC3.39 | IC1.37 19.45,56.37 v21.52,54.3 | v44.68,62.76 44.84,62.91 44.84,64.44 47.2,66.8 47.2,67.63 IC3.39
  Bottom 0.152: v21.52,54.3 21.52,55.06 22.66,56.21 24.41,56.21 24.87,56.66 31.88,56.66 36.61,61.39 36.61,64.82 39.88,68.09 44.3,68.09 48.19,71.98 48.19,72.82 47.02,73.99 J5.33 | v44.68,50.87 44.68,52.17 44.23,52.62 44.23,62.3 v44.68,62.76
A11  (via drill 0.4)
  Top 0.152: J5.34 47.05,72.33 47.05,72.36 46.43,71.74 46.44,70.75 IC3.40 | IC1.38 18.95,55.57 v20.6,53.92 | IC4.25 49.1,43.78 43.92,48.97 v43.92,51.48 | 46.51,67.33 46.43,67.41 IC3.40 | v44.07,63.52 44.23,63.67 44.23,64.59 46.44,66.8 46.44,67.66 IC3.40
  Bottom 0.152: v20.6,53.92 20.6,54.83 22.43,56.66 24.19,56.66 24.64,57.12 31.65,57.12 36.15,61.62 36.15,65.05 39.65,68.55 43.01,68.55 46.82,72.36 J5.34 | v43.92,51.48 43.92,52.24 43.77,52.4 43.77,63.22 v44.07,63.52
A12  (via drill 0.4)
  Top 0.152: J5.35 45.6,73.78 45.6,67.7 IC3.41 | IC1.39 18.45,54.77 v19.69,53.54 | IC4.4 42.37,48.87 43.16,49.65 v43.16,52.09 | 45.6,67.41 45.63,67.44 IC3.41 | v43.46,64.28 43.46,64.59 45.6,66.72 45.6,67.56 45.63,67.59 IC3.41
  Bottom 0.152: v19.69,53.54 19.69,54.6 22.2,57.12 23.96,57.12 24.41,57.58 31.42,57.58 35.69,61.84 35.69,65.27 39.43,69.01 42.78,69.01 45.75,71.98 45.75,72.51 44.48,73.78 J5.35 | v43.16,52.09 43.31,52.24 43.31,64.13 v43.46,64.28
A13  (via drill 0.4)
  Top 0.152: 44.84,72.05 44.53,72.36 J5.36 44.79,72.05 44.84,72.05 | IC1.40 17.96,53.97 v18.78,53.16 | v46.97,49.04 46.97,48.66 48.04,47.59 IC4.28 | IC3.42 44.84,72.05 | 44.84,67.48 44.83,67.49 IC3.42 | v42.85,65.05 43.16,65.05 44.84,66.72 44.84,67.41 44.83,67.41 IC3.42
  Bottom 0.152: v18.78,53.16 18.78,54.38 21.98,57.58 23.73,57.58 24.19,58.03 31.2,58.03 35.23,62.07 35.23,65.5 39.2,69.46 41.94,69.46 44.48,72 J5.36 | v42.85,65.05 42.63,64.82 42.63,64.05 42.85,63.83 42.85,52.78 42.4,52.32 42.4,51.86 45.52,48.74 46.66,48.74 v46.97,49.04
A14  (via drill 0.4)
  Top 0.152: J5.37 43.31,73.53 43.31,71.6 44.07,70.84 44.07,67.71 IC3.43 | IC1.41 17.46,53.17 v17.86,52.78
  Bottom 0.152: v17.86,52.78 17.86,54.15 21.75,58.03 23.58,58.03 24.03,58.49 30.97,58.49 34.78,62.3 34.78,65.73 38.97,69.92 41.71,69.92 43.31,71.52 43.31,72.74 41.94,74.11 J5.37
A15  (via drill 0.4)
  Top 0.152: J5.38 41.94,71.45 43.23,70.15 IC3.44 | IC1.42 15.26,52.4 v16.95,52.4
  Bottom 0.152: v16.95,52.4 16.95,53.92 21.52,58.49 23.35,58.49 23.8,58.95 30.59,58.95 34.32,62.68 34.32,65.96 38.74,70.38 41.33,70.38 41.94,70.99 J5.38
AC1
  Top 1.778: J2.1 81.87,32.99 F1.1
  Bottom 1.27: J2.1 84.46,30.45 | J2.1 | JP3.4 75.23,30.45 J2.1
AC2  (via drill 0.61)
  Top 0.61: v67.34,32.99 D3.A
  Top 0.813: v67.34,32.99 67.34,32.76 D7.C 63.75,29.02 63.73,29 63.75,28.98 D6.A
  Bottom 0.813: JP3.1 79.28,18.65 79.28,24.96 83.39,24.96 86.52,28.09 88.12,28.09 90.48,30.45 J2.2
  Bottom 1.422: J2.3 69.5,35.15 v67.34,32.99
  Bottom 1.778: J2.3 87.51,35.17 90.52,35.17 J2.2
ACF
  Top 0.813: F1.2 78.75,25.34 75.39,25.34 75.39,25.35 D4.A 75.39,25.39 75.39,29.16 D5.C 75.39,29.2 75.39,32.98 D3.C
AGND5  (via drill 0.4)
  Top 0.406: IC1.63 28.43,44.38 27.46,43.4 C5.2 27.26,43.15 27.46,43.17 v27.46,42.03 | R3.2 13.59,45.3 v13.59,48.36
  other vias: 22.05,48.28
  pour Ground (isolate 0.305): 0.67,69.82 6.38,69.82 12.09,64.11 12.09,49.5 29.88,49.5 29.88,41.24 0.67,41.24
  pour Top (isolate 0.305): 12.09,64.11 6.38,69.82 0.67,69.82 0.67,41.24 28.61,41.24 28.61,49.5 12.09,49.5
  pour Bottom (isolate 0.305): 12.09,64.11 12.09,49.5 28.61,49.5 28.61,41.24 0.67,41.24 0.67,69.82 6.38,69.82
ALE  (via drill 0.4)
  Top 0.152: IC1.43 15.17,51.63 | IC1.43 15.22,51.56 | IC3.1 43.01,65.97 v43.16,66.11 | IC1.43 15.21,51.57 15.19,51.56 v13.52,51.56
  Bottom 0.152: v43.16,66.11 42.63,66.64 40.57,66.64 37.98,64.05 37.98,60.7 32.57,55.29 25.56,55.29 25.1,54.83 24.11,54.83 23.58,54.3 17.02,51.56 v13.52,51.56 12.68,52.4 12.68,61.39 11,63.06 11,64.28 9.55,65.73 R34*.2
AREF  (via drill 0.4)
  Top 0.305: IC1.62 27.63,44.57 27.31,44.24 26.62,44.24 v25.94,43.56
  Bottom 0.406: v25.94,43.56 25.33,42.95 5.29,42.95 3.84,44.39 J6.2
AVCC3  (via drill 0.4)
  Top 0.152: C13.1 51.55,25.56 53.34,23.77 FB4.1 53.29,23.21 v53.29,22.6 | R20.2 56.57,9.95 56.57,10.94 R15.2 57.03,11.1 v57.64,11.1 58.32,11.1 TR1.15
  Top 0.203: IC2.16 48.87,18.57 48.87,18.56 51.91,18.56 C10.1 | IC2.11 49.27,16.57 50.02,15.82 50.02,15.44 50.01,15.43 C11.1
  Top 0.406: C11.1 50.01,13.93 v50.02,13.92 | C10.1 51.91,18.64 51.92,18.64 v51.92,19.63 | LED4.A 54.28,4.64 v54.28,6.68 | LED3.A 64.34,4.74 v64.34,6.68
  Supply 0.305: J1.D2- 94.21,17.42 J1.D1- 92.82,12.7 89.49,12.7 82.02,5.23 65.87,5.23 64.42,6.68 v64.34,6.68
  pour Supply (isolate 0.305): 44.48,22.83 62.9,22.83 62.9,7.59 64.8,7.59 64.8,1.24 52.1,1.24 52.1,12.67 44.48,12.67
  pour Top (isolate 0.305, no thermals): 63,5.76 66.04,5.76 66.04,1.8 63,1.8
  pour Top (isolate 0.305, no thermals): 52.91,5.76 55.96,5.76 55.96,1.8 52.91,1.8
AVCC5  (via drill 0.4)
  Top 0.406: 29.24,43.15 C5.1 | IC1.64 29.24,43.15 | 29.24,43.15 arc90 29.14,43.05 v29.14,42.03 | J6.1 6.41,44.42 6.43,44.39 7.42,45.38 FB2.2
  pour Supply (isolate 0.305, rank 2, no thermals): 5.11,48.23 11.46,48.23 11.46,45.05 16.54,45.05 16.54,40.61 19.4,40.61 20.67,41.88 20.67,45.05 29.88,45.05 29.88,39.98 14,39.98 14,42.52 5.11,42.52
CYCLE\
  Top 0.152: IC2.35 45.43,27.42 44.84,28.01 44.61,28.01 44.41,28.21 RN1.8
D0  (via drill 0.4)
  Top 0.152: IC2.76 | IC2.76 | IC1.51 18.87,45.61 18.93,45.61 18.93,47.21 23.8,52.09 v23.8,53.54 | IC2.107 | IC2.107 | IC2.107 | IC2.107 37.83,12.93 39.27,14.37 40.34,14.37 v40.57,14.6 | IC2.76 39.68,20.57 v40.57,21.46 | v38.44,37.46 41.28,37.46 IC4.13 41.33,37.46 45.29,37.46 45.6,37.77 49.41,37.77 v49.56,37.92 | IC3.27 54.44,61.17 55.2,61.92 v56.42,61.92
  Bottom 0.152: J5.15 69.86,74.9 68.38,73.43 68.38,71.75 65.26,68.63 60.46,68.63 58.09,66.34 58.09,63.6 v56.42,61.92 54.74,60.24 54.74,44.39 49.56,39.21 v49.56,37.92 | v40.57,14.6 v40.57,21.46 40.57,24.05 38.44,26.18 38.44,34.18 38.59,34.34 38.59,37.31 v38.44,37.46 38.44,44.47 30.66,52.24 25.1,52.24 v23.8,53.54
D1  (via drill 0.4)
  Top 0.152: IC2.75 | IC2.75 | 52.99,58.02 52.99,58.03 52.98,58.03 52.99,58.02 | 52.99,58.02 IC3.23 | IC1.50 18.07,45.61 18.09,45.61 18.09,47.06 22.89,51.86 22.89,53.16 22.88,53.16 v22.88,53.18 | 53.06,58.02 53.06,58.03 | 53.06,58.02 52.99,58.02 | v55.5,57.96 53.06,57.96 53.06,58.02 | IC2.106 37.43,13.37 38.89,14.83 39.43,14.83 v39.65,15.06 | IC2.75 38.71,20.97 v39.65,21.92 | IC4.14 | v37.83,36.16 IC4.14 | IC4.14 | IC4.14 47.27,36.16 47.66,36.55 v50.32,36.55
  Bottom 0.152: J5.16 69.83,72.36 65.64,68.17 60.69,68.17 58.55,66.11 58.55,63.06 55.5,60.02 v55.5,57.96 55.2,57.65 55.2,44.17 50.32,39.29 v50.32,36.55 | v39.65,15.06 v39.65,21.92 39.65,24.2 37.83,26.03 37.83,34.34 37.98,34.49 37.98,36.01 v37.83,36.16 37.67,36.32 37.67,37.92 37.83,38.07 37.83,44.39 30.43,51.79 24.26,51.79 22.88,53.16 v22.88,53.18
D2  (via drill 0.4)
  Top 0.152: IC2.74 | IC2.74 | 52.91,62.76 IC3.29 52.91,62.76 | v55.05,62.76 52.91,62.76 | IC1.49 17.25,45.57 17.25,46.91 21.98,51.63 21.98,52.62 22.01,52.66 v22.01,52.8 | IC2.105 37.03,13.81 v38.74,15.52 | IC2.74 37.74,21.37 v38.74,22.37 | v37.22,34.95 41.25,34.95 IC4.15 41.33,34.87 48.19,34.87 48.42,35.1 v49.41,35.1
  Bottom 0.152: J5.17 66.02,73.58 66.02,71.52 64.19,69.54 60,69.54 57.18,66.8 57.18,64.51 55.43,62.76 v55.05,62.76 53.83,62.76 53.52,62.45 53.52,61.69 53.83,61.39 53.83,44.85 48.34,39.37 48.34,36.7 49.41,35.63 v49.41,35.1 | v38.74,15.52 v38.74,22.37 38.74,24.35 37.22,25.88 37.22,32.2 37.37,32.35 37.37,34.79 v37.22,34.95 37.06,35.1 37.06,38.07 37.22,38.22 37.22,44.32 30.21,51.33 23.5,51.33 22.03,52.8 v22.01,52.8
D3  (via drill 0.4)
  Top 0.152: IC2.73 | IC2.73 | 52.96,62 IC3.28 53.45,62 v54.28,62 | IC1.48 15.27,47.61 15.27,47.67 17.33,47.67 21.06,51.41 v21.06,52.4 | IC2.104 36.63,14.8 37.8,15.97 v37.83,15.97 | IC2.73 36.77,21.77 v37.83,22.83 | v36.61,32.89 48.95,32.89 49.71,33.65 v50.32,33.65 52.68,33.65 IC4.17
  Bottom 0.152: J5.18 67.34,71.85 64.57,69.08 60.23,69.08 57.64,66.57 57.64,64.21 55.43,62 v54.28,62 54.28,44.62 48.8,39.14 48.8,36.93 50.32,35.4 v50.32,33.65 | v37.83,15.97 v37.83,22.83 37.83,24.51 36.61,25.73 v36.61,32.89 36.76,33.04 36.76,34.41 36.45,34.72 36.45,35.17 36.61,35.33 36.61,44.24 29.98,50.87 22.59,50.87 v21.06,52.4
D4  (via drill 0.4)
  Top 0.152: IC2.71 | IC2.71 | 52.92,64.36 IC3.31 | 52.92,64.36 52.91,64.36 | 52.99,64.28 52.92,64.35 52.92,64.36 | v55.05,64.36 53.06,64.36 52.99,64.28 | 52.99,64.28 52.99,64.36 | IC1.47 15.37,48.51 15.45,48.43 17.4,48.43 20.15,51.18 v20.15,52.02 | IC2.102 35.83,15.36 v36.91,16.44 v36.91,16.43 | IC2.71 36.19,22.57 v36.91,23.29 | v36,34.26 39.35,34.26 39.5,34.41 40.11,34.41 40.26,34.26 v48.65,34.26 49.71,34.26 50.35,34.89 IC4.18
  Bottom 0.152: J5.19 64.8,74.27 63.51,72.97 63.51,72.05 61.98,70.45 59.54,70.45 56.27,67.25 56.27,64.97 55.66,64.36 v55.05,64.36 54.06,64.36 52.61,62.91 52.61,61.23 52.91,60.93 52.91,45.31 47.43,39.82 47.43,38.22 47.27,38.07 47.27,35.33 48.34,34.26 v48.65,34.26 | v36.91,16.43 v36.91,23.29 36.91,24.66 36,25.57 36,32.2 35.84,32.35 35.84,34.11 v36,34.26 36,35.33 36.15,35.48 36.15,36.16 36,36.32 36,44.17 29.75,50.41 21.75,50.41 v20.15,52.02
D5  (via drill 0.4)
  Top 0.152: IC2.70 | IC2.70 | IC4.19 52,36.17 51.39,36.16 51.01,36.16 50.63,35.78 v48.04,35.78 47.81,35.55 38.74,35.55 38.66,35.48 37.6,35.48 37.29,35.78 v35.39,35.78 | 52.91,63.52 52.91,63.55 IC3.30 52.93,63.54 52.91,63.52 | v54.28,63.52 52.91,63.52 | IC1.46 15.26,49.2 17.48,49.2 19.23,50.95 v19.23,51.63 | IC2.101 35.43,15.7 36,16.26 v36,16.89 | IC2.70 35.22,22.97 v36,23.74
  Bottom 0.152: J5.20 64.8,71.14 63.73,70 59.77,70 56.72,67.03 56.72,64.74 55.5,63.52 v54.28,63.52 53.9,63.52 53.06,62.68 53.06,61.46 53.37,61.16 53.37,45.08 47.88,39.59 47.88,35.94 v48.04,35.78 | v36,16.89 v36,23.74 36,24.73 35.31,25.42 35.39,32.05 35.23,32.2 35.23,35.63 v35.39,35.78 35.54,35.94 35.54,37.54 35.39,37.69 35.39,44.09 29.52,49.96 20.91,49.96 v19.23,51.63
D6  (via drill 0.4)
  Top 0.152: IC2.69 | IC2.69 | 15.33,49.97 | 15.33,49.97 IC1.45 | 52.73,37.47 IC4.20 52,37.46 50.17,37.46 49.71,37 v45.9,37 45.67,36.77 38.13,36.77 37.9,37 v34.78,37 | IC3.33 52.91,65.96 | IC3.33 | v55.05,65.96 IC3.33 | 15.33,49.97 15.34,49.96 17.56,49.96 18.32,50.72 v18.32,51.25 | IC2.100 35.03,17.32 35.08,17.37 v35.08,17.34 | IC2.69 34.25,23.37 v35.08,24.2
  Bottom 0.152: J5.21 60.99,73.63 60.99,71.9 60.46,71.29 59.09,71.29 55.35,67.64 55.35,66.26 v55.05,65.96 54.06,65.96 51.69,63.6 51.69,60.78 52,60.47 52,45.77 45.9,39.67 v45.9,37 | v35.08,17.34 v35.08,24.2 35.08,24.81 34.78,25.12 34.78,35.17 34.62,35.33 34.62,36.85 v34.78,37 34.93,37.16 34.93,38.68 34.78,38.83 34.78,44.01 29.29,49.5 20.07,49.5 v18.32,51.25
D7  (via drill 0.4)
  Top 0.152: IC2.68 | IC2.68 | IC1.44 | IC1.44 | v54.28,65.2 52.96,65.2 IC3.32 52.88,65.12 | 52.7,38.67 IC4.21 52.71,38.68 v46.66,38.68 45.98,38.68 45.37,38.07 39.04,38.07 38.89,38.22 v34.17,38.22 | 15.27,50.8 15.25,50.77 IC1.44 | 15.27,50.8 15.29,50.78 | 15.27,50.8 15.35,50.87 v17.4,50.87 | IC2.99 34.63,16.65 34.17,17.11 v34.17,17.8 | IC2.68 32.47,23.77 32.49,23.74 33.56,23.74 34.17,24.35 v34.17,24.66
  Bottom 0.152: J5.22 60.97,70.91 59.39,70.91 55.81,67.48 55.81,65.65 55.35,65.2 v54.28,65.2 54.21,65.2 52.15,63.14 52.15,61.01 52.46,60.7 52.46,45.54 46.66,39.75 v46.66,38.68 | v34.17,17.8 v34.17,24.66 34.17,36.39 33.86,36.7 33.86,37.16 34.17,37.46 v34.17,38.22 34.17,43.94 29.06,49.04 19.23,49.04 v17.4,50.87
DC  (via drill 0.4, 0.61)
  Top 0.406: 58.7,29.76 58.54,29.14 C19.+
  Top 0.61: JP6.1 13.25,10.5 13.21,10.45 13.97,9.69 13.97,7.83 14.09,7.7 D2.C | D4.C D6.C 67.8,23.15 | v64.19,23.13 64.17,23.15 67.8,23.15 | 67.8,23.15 68.92,23.15 68.84,23.13 v84.46,23.13
  Top 0.813: v14,1.56 14,7.59 D2.C | v64.19,31.67 62.67,31.67 60.76,29.76 58.7,29.76 | IC8.3 67.82,41.88 67.66,41.72 66.23,41.72 66.2,41.69 C33.1 66.07,39.98 66.02,40.03 v66.02,40.05
  Bottom 0.61: R30*.1 96.65,54.1 96.65,54.07
  Bottom 0.813: J5.10 77.5,71.55 78.97,70.07 79.96,70.07 90.02,70.15 90.94,70.15 96.65,64.44 96.65,54.07 96.65,28.32 94.21,25.88 86.29,25.88 84.46,24.05 v84.46,23.13 84.46,21.92 86.67,19.71 86.67,17.95 86.59,9.88 78.59,1.57 72.27,1.57 v14,1.56 | v66.02,40.05 64.19,38.15 v64.19,31.67 v64.19,23.13
DCX
  Top 0.813: JP6.2 11.23,10.58 11.23,10.13 10.09,10.13 | J4.4 10.09,10.13 | D2.A 10.09,10.13
DE485
  Top 0.152: 24.11,22.83 JP2.4 | JP2.2 22.21,22.83 24.11,22.83 | IC7.3 25.68,15.85 24.87,16.66 24.87,17.88 25.56,18.56 26.85,18.56 R27.2 27.12,18.91 27.16,18.94 27.16,21.61 26.85,21.92 25.02,21.92 24.11,22.83
DFCS\  (via drill 0.4)
  Top 0.152: v25.94,27.33 24.03,27.33 IC13.4 | IC12.1 26.84,36.48 v27.73,35.59 28.61,34.72 28.61,34.56 | 28.61,34.56 | 28.61,34.56 IC11.4
  Bottom 0.152: v25.94,27.33 27.39,28.77 27.39,35.25 v27.73,35.59
DFSO  (via drill 0.4)
  Top 0.152: 29.82,31.06 29.85,31.08 IC13.8 29.37,31.14 28.38,31.14 27.16,32.35 v23.96,32.35 | IC12.2 24.16,35.61 v23.96,35.4
  Bottom 0.152: v23.96,32.35 v23.96,35.4
DIHO  (via drill 0.4)
  Top 0.152: IC6.11 77.5,66.09 77.53,66.11 77.53,66.8 77.75,67.03 79.2,67.03 79.43,66.8 79.43,62.15 76.23,58.95 64.82,58.95 JP1.4 | v25.71,17.19 26.32,17.19 IC7.4
  Bottom 0.152: JP1.4 63.61,57.93 63.58,57.96 63.51,57.88 59.16,57.88 58.86,57.58 58.86,56.81 59.47,56.21 59.47,43.94 53.37,37.84 53.37,26.03 48.04,20.7 45.6,20.7 45.29,20.39 45.29,19.1 42.4,16.2 42.4,13.92 40.19,11.71 27.92,11.71 25.71,13.92 v25.71,17.19
EXPALE
  Bottom 0.152: J5.64 9.55,71.72 R34*.1
GND  (via drill 0.4, 0.61, 0.8)
  Top 0.152: IC2.103 36.23,9.31 C15.2 | IC2.57 36.61,26.39 36.61,28.01 36.41,28.01 C6.2 | 40.49,9.18 C16.2 40.48,9.26 40.49,9.27 40.49,9.8 40.72,10.03 41.71,10.03 41.83,10.15 IC2.117 41.83,12.19 41.56,12.47 38.51,12.47 38.23,12.19 IC2.108 | C17.2 43.62,9.18 v43.62,8.05 | IC2.24 47.66,21.77 47.66,21.76 45.75,21.76 45.6,21.92 v45.53,21.92 | IC1.22 25.25,61.62 | 27.89,3.32 S1.3 | S1.4 17.89,3.32 27.89,3.32 | 27.89,3.32 29.29,3.32 v29.75,2.87 | IC2.6 46.09,14.57 v46.05,14.6 | IC2.13 46.08,17.37 v46.05,17.34 | C9.2 30.71,22.17 IC2.72 | C7.2 38.58,28.09 38.63,28.09 IC2.52 | IC2.42 42.63,25.19 42.85,24.96 v43.77,24.96 | IC2.37 44.63,25.14 44.45,24.96 v43.77,24.96 | IC2.39 43.83,25.03 v43.77,24.96 | IC2.67 30.71,24.17 30.51,23.97 v30.51,23.44 | IC2.19 46.2,19.77 v46.05,19.63 | IC2.82 31.03,18.17 31.03,17.8 | 31.03,17.77 31.03,17.37 IC2.84 | 31.03,17.8 31.03,17.77 | IC2.84 | IC2.84 | 31.03,17.77 IC2.83 | 31.03,17.77 | IC2.87 31.03,16.17 31.03,15.77 | 31.03,14.17 31.03,13.77 IC2.93 | 31.03,14.57 31.03,14.17 | 31.03,14.91 31.03,14.57 | 31.03,14.91 31.03,14.97 | 31.03,14.97 31.03,15.37 | 31.03,15.37 31.03,15.77 | IC2.93 | IC2.93 | 31.03,14.17 IC2.92 | 31.03,14.17 | 31.03,14.57 IC2.91 | 31.03,14.57 | 31.03,14.97 IC2.90 | 31.03,14.97 | 31.03,15.37 IC2.89 | 31.03,15.37 | 31.03,15.77 IC2.88 | 31.03,15.77 | 31.03,17.8 31.04,17.8 | v30.21,17.8 31.03,17.8 | 31.03,14.91 31.04,14.91 | v30.21,14.91 31.03,14.91
  Top 0.305: 25.25,61.59 25.25,61.62 25.25,64.13 | 36.3,9.18 C15.2 | C16.2 40.42,9.18 v40.42,8.05 | 24.03,64.05 C2.2 24.06,64.13 25.25,64.13 | v25.86,65.2 25.86,65.12 25.42,65.11 C3.2 25.17,64.13 25.25,64.13 | 38.59,29.69 37.22,29.69 36.45,28.93 36.45,28.47 36.41,28.43 C6.2 | 38.59,29.69 v39.81,29.69 | C7.2 38.58,29.68 38.59,29.69 | R7.1 32.1,31.45 32.11,31.44 32.1,31.43 32.1,30.75 | 32.1,30.75 C37.2 31.93,29.81 IC13.7 | 32.1,30.75 v33.33,30.75 | R27.1 30.21,18.7 v30.21,17.8 | IC10.2 60.3,61.01 v60.3,62 | v80.73,53.92 83.7,53.92 86.14,51.48 86.14,49.35 J3.5 | IC12.3 23.51,37.45 v23.2,37.77 | IC11.3 28.59,37.48 v28.3,37.77 | IC5.3 29.75,4.08 v29.75,2.87
  Top 0.406: C32.2 24.98,9.37 v24.95,9.34 | 57.33,39.34 57.33,39.44 58.55,39.44 | C20.- 57.87,48.2 57.87,46.84 v57.64,46.6 | 52.29,69.77 C40.2 52.48,69.82 52.53,69.77 v53.68,69.77 | 56.08,51.25 56.11,51.25 | 56.08,51.25 v56.88,51.25 | C38.2 54.68,51.25 56.08,51.25 | 66.09,35.78 66.09,35.95 C35.2 65.88,35.78 63.73,35.78 IC9.2 57.26,35.55 57.23,35.53 IC9.4 | IC6.16 71.15,67.73 C23.2 71.12,68.21 v71.12,69.16 | C11.2 51.65,14.03 51.69,13.99 | 51.69,13.99 51.68,13.98 v51.66,13.98 | C12.2 51.65,13.95 51.69,13.99 | R9.1 53.69,12.01 v53.68,12.01 | C10.2 arc-90 53.52,18.42 v53.52,19.63 | C14.2 35.61,7.28 v35.92,7.59 36.3,7.97 36.3,9.18 | v64.8,47.06 65.98,47.06 C34.2 66.23,46.98 v67.62,46.98 69.77,46.98 IC8.1 69.64,47.14 | C33.2 65.98,43.25 v64.8,43.25 | IC4.16 41.28,33.65 v39.81,33.65 | v57.1,59.1 55.66,59.1 55.66,59.15 C41.2 55.3,59.15 55.27,59.18 54.97,59.18 54.59,59.56 52.99,59.56 52.98,59.57 IC3.25 | C31.1 79.3,53.92 v80.73,53.92 | C8.2 46.2,30 46.21,30.3 v47.35,30.3 | 58.48,24.11 C19.- | C9.2 v30.51,23.44 | LED1.C v84,3.78 | 58.55,39.44 | C36.- 58.55,39.44 | 20.43,43.78 20.22,43.78 C4.2 | 20.43,43.78 IC1.53 | 20.43,43.78 20.45,43.78 | v47.27,53.31 47.27,54.22 47.28,54.22 C39.2 47.28,54.76 | 47.28,54.76 47.35,54.76 | IC3.17 47.23,54.76 47.28,54.76 | C1.2 15.96,64.18 v15.96,65.27 | R23.1 19.39,18.38 19.39,18.33 19.77,18.33 19.77,18.38 v21.3,18.38 v21.29,18.38 IC7.5 | C18.2 51.69,9.18 v51.69,10.79 | IC3.4 40.23,63.57 v40.19,63.52
  Top 0.61: R26.2 v20.98,10.77 | C19.- 58.47,24.12 | 71.78,29.18 D5.A D7.A | R3.1 v13.67,39.59 | C4.2 v20.22,39.59
  Top 0.813: v58.48,21.92 58.48,24.11 | D7.A 67.75,29.36 68.01,29.4 v68.01,31.25
  Bottom 0.406: R32*.1 93.98,36.3 v93.98,34.72 | R33*.1 62.22,20.61 62.21,20.62 v60.84,20.62
  other vias: 55.91,38.7 57.18,38.7 58.45,38.7 59.72,38.7 55.91,32.35 57.18,32.35 58.45,32.35 59.72,32.35 70.74,62.45 70.74,61.23 70.74,60.02 47.12,50.49 21.29,67.56 32.11,64.89 13.52,52.85 38.59,12.54 43.16,12.62 45.98,33.57 69.83,48.59 67.54,35.94 1.63,74.57 2.93,75.87 4.75,75.87 6.05,74.57 6.05,72.66 4.75,71.37 2.93,71.37 1.63,72.66 1.63,4.77 2.93,6.07 4.75,6.07 6.05,4.77 6.05,2.87 4.75,1.57 2.93,1.57 1.63,2.87 91.77,74.57 93.07,75.87 94.9,75.87 96.19,74.57 96.19,72.66 94.9,71.37 93.07,71.37 91.77,72.66 91.77,4.69 93.07,5.99 94.9,5.99 96.19,4.69 96.19,2.79 94.9,1.49 93.07,1.49 91.77,2.79 26.4,69.31
  pour Ground (isolate 0.305): 0.67,77.44 97.19,77.44 97.19,69.82 81.95,69.82 81.95,36.8 97.19,36.8 97.19,24.73 90.52,24.73 89.25,26 86.39,26 85.12,24.73 62.9,24.73 62.9,5.68 85.12,5.68 86.39,4.42 88.93,4.42 90.2,5.68 97.19,5.68 97.19,0.6 0.67,0.6 0.67,39.98 31.14,39.98 31.14,50.77 13.37,50.77 13.37,64.74 7.02,71.09 0.67,71.09
  pour Top (isolate 0.203, rank 3, no thermals): 60.99,31.72 55.27,31.72 55.27,39.34 60.99,39.34
  pour Top (isolate 0.305, rank 2, no thermals): 79.95,5.76 83,5.76 83,1.8 79.95,1.8
  pour Top (isolate 0.305, rank 2): 0.67,77.44 97.19,77.44 97.19,69.82 81.95,69.82 81.95,52.67 70.83,52.67 70.83,36.16 97.19,36.16 97.19,24.73 90.52,24.73 89.25,26 86.39,26 85.12,24.73 62.9,24.73 62.9,5.68 78.77,5.68 78.77,1.56 82.9,1.56 82.9,5.68 85.12,5.68 86.39,4.42 88.93,4.42 90.2,5.68 97.19,5.68 97.19,0.6 0.67,0.6 0.67,39.98 29.88,39.98 29.88,50.77 13.37,50.77 13.37,64.74 7.02,71.09 0.67,71.09
  pour Bottom (isolate 0.305, rank 2): 0.67,77.44 97.19,77.44 97.19,69.82 71.78,69.82 71.78,36.8 97.19,36.8 97.19,24.73 90.52,24.73 89.25,26 86.39,26 85.12,24.73 62.9,24.73 62.9,5.68 85.12,5.68 86.39,4.42 88.93,4.42 90.2,5.68 97.19,5.68 97.19,0.6 0.67,0.6 0.67,39.98 29.88,39.98 29.88,50.77 13.37,50.77 13.37,64.74 7.02,71.09 0.67,71.09
HI
  Top 0.152: IC6.10 78.77,65.53 78.75,65.5 78.75,64.51 77.91,63.67 67.62,63.67 65.88,61.93 JP1.7
LEDA\
  Top 0.152: LED4.C 59.39,2.33 61.6,2.33 R17.2 61.62,1.77 62.44,0.96 83.93,0.96 85.37,2.41 85.37,7.74 90.25,12.62 95.05,12.62 95.89,11.78 95.89,8.96 95.92,8.94 J1.D1+
  pour Top (isolate 0.305, no thermals): 57.18,5.76 60.23,5.76 60.23,1.8 57.18,1.8
LEDB\
  Top 0.152: LED3.C 69.55,2.33 71.76,2.33 R18.2 71.78,1.82 72.27,1.34 83.62,1.34 84.92,2.64 84.92,7.97 90.02,13.08 93.3,13.08 94.21,13.99 J1.D2+
  pour Top (isolate 0.305, no thermals): 67.26,5.76 70.31,5.76 70.31,1.72 67.26,1.72
MR\  (via drill 0.4)
  Top 0.152: S1.2 17.89,7.89 27.89,7.89 S1.1 28.38,8.42 v28.38,10.41 | IC10.4 59.39,58.34 59.39,57.35 v59.62,57.12 60.61,56.13 61.52,56.13 v62.21,55.44
  Bottom 0.152: J5.9 76.23,73.63 76.23,71.83 68.31,63.9 68.31,55.75 67.39,54.83 62.82,54.83 v62.21,55.44 | v59.62,57.12 59.92,56.81 59.92,43.71 53.83,37.61 53.83,25.8 46.89,18.87 45.75,18.87 42.85,15.97 42.85,13.76 40.34,11.25 29.21,11.25 v28.38,10.41 24.72,14.07 24.72,18.26 23.5,19.48 21.37,19.48 16.79,24.05 9.63,24.05 8.87,24.81 8.87,29.13 J7.6
N$1
  Top 0.152: C28.2 69.22,54.37 69.22,57.27 69.52,57.58 70.82,57.58 71.12,57.27 71.12,56.51 71.15,56.48 IC6.3
N$2
  Bottom 0.61: J3.9 90.25,49.2 92.31,51.25 R30*.2
N$4
  Top 0.152: IC1.19 27.63,61.75 27.61,61.77 27.61,62.61 27.84,62.84 28.15,62.84 28.68,63.37 31.12,63.37 32.47,62.02 Y2.1
N$5
  Top 0.152: TR1.1 68.69,9.5 69.91,8.28 80.65,8.28 83.16,10.79 84.08,10.79 84.1,10.77 J1.1
N$6
  Top 0.152: C2.1 22.39,63.79 22.43,63.75 22.43,63.37 22.59,63.22 24.03,63.22 24.43,62.81 IC1.23 | C2.1 22.36,64.13 20.91,64.13 R1.2 | Y1.P$2 23.54,67.6 22.36,66.42 22.36,64.28 22.38,64.26 C2.1
N$10
  Top 0.152: IC1.24 23.63,62.62 23.42,62.84 22.28,62.84 22.05,63.06 19.61,63.06 19.16,63.52 19.16,63.9 19.18,63.93 R1.1 | R1.1 19.23,64.05 | R1.1 19.23,64.11 19.23,64.13 | Y1.P$1 19.23,67.6 19.23,64.13 | 19.23,64.13 19.21,64.13 R1.1 | C1.1 17.71,64.13 19.23,64.13
N$12
  Top 0.152: TR1.3 68.97,12.04 69.98,11.02 72.34,11.02 73.33,12.01 81.56,12.01 81.64,12.09 81.69,12.04 J1.2
N$15
  Top 0.152: C31.2 77.63,53.97 76.23,55.37 IC6.7
N$20  (via drill 0.4)
  Top 0.152: R25.1 16.07,13.62 v14.84,13.62
  Bottom 0.152: v14.84,13.62 14.43,14.04 14.43,17.34 13.25,18.52 JP6.9
N$22
  Top 0.152: TR1.6 69.17,15.85 70.06,16.73 73.56,16.73 74.1,16.2 78.59,16.2 81.49,13.31 84.23,13.31 84.31,13.23 84.38,13.31 J1.3
N$23
  Top 0.152: IC1.18 28.43,62.44 28.91,62.91 30.82,62.91 31.27,62.45 31.27,61.46 Y2.4
N$24
  Top 0.152: TR1.8 68.74,18.38 69.98,19.63 72.42,19.63 74.94,17.11 J1.6
N$25
  Top 0.152: IC2.12 49.78,16.97 50.47,16.28 53.06,16.28 53.68,15.67 53.68,15.06 53.69,15.04 R9.2
N$26
  Top 0.152: TR1.7 69.14,17.11 70.21,18.18 70.74,18.18 70.78,18.22 R21.2
N$27
  Top 0.152: R10.2 56.91,17.54 57.79,18.41 58.78,18.41 58.81,18.38 TR1.9
N$31
  Top 0.152: IC6.2 69.88,55.16 70.59,54.45 70.59,54.22 70.64,54.17 C29.1
N$32
  Top 0.152: TR1.2 69.17,10.77 70.21,9.72 70.74,9.72 70.81,9.66 R22.2
N$33
  Top 0.152: R11.2 57.03,14.6 57.94,15.52 58.32,15.52 TR1.11
N$43
  Top 0.152: LED1.A 78,3.73 75.8,2.66 R28.1
  pour Top (isolate 0.305, no thermals): 78.73,5.76 75.68,5.76 75.68,1.8 78.73,1.8
N$44
  Top 0.152: R22.1 71.15,12.82 71.12,12.85 71.15,12.87 R21.1 71.14,15.36 | C21.1 77.5,13.94 75,13.94 C22.1 73.58,15.36 71.14,15.36 | 71.14,15.36 71.12,15.36
N$56
  Top 0.152: C29.2 72.29,54.1 72.42,54.22 IC6.4
N$57
  Top 0.152: C30.2 75.78,54.44 75.01,55.21 75.01,55.98 74.96,56.03 IC6.6
N$58
  Top 0.152: C30.1 74.14,54.8 73.72,55.21 73.72,55.82 73.69,55.85 IC6.5
N$68
  Top 0.152: R23.2 15.27,18.38 13.52,16.64 13.32,16.64 JP6.7
N$70
  Top 0.152: R24.2 15.27,15.85 14,14.58 JP6.5 | JP6.5
NICINT  (via drill 0.4)
  Top 0.152: IC2.29 47.45,23.77 47.43,23.74 45.83,23.74 45.37,23.29 41.94,23.29 v41.48,22.83 | v39.65,38.91 38.74,38.91 38.13,39.52 R2.2
  Bottom 0.152: v41.48,22.83 41.48,23.9 39.04,26.33 39.04,33.95 39.65,34.56 v39.65,38.91 40.04,39.29 R31*.2
NICSEL\  (via drill 0.4)
  Top 0.152: IC2.41 43.01,26.39 | IC2.41 43.01,26.37 | IC2.41 43.01,27.1 v43.01,27.78 42.81,28.06 RN1.6 | IC3.2 41.5,65.2 v40.19,65.2
  Bottom 0.152: v40.19,65.2 40.57,65.2 42.4,63.37 42.4,53.16 41.94,52.7 41.94,28.93 v43.01,27.78
NICWR\
  Top 0.152: IC2.36 45.03,27.28 44.76,27.55 44.3,27.55 43.61,28.25 RN1.7
NLEDA\  (via drill 0.4)
  Top 0.152: IC2.22 46.4,20.97 44.99,19.55 44.99,14.14 v45.45,13.69 | R17.1 61.6,5.23 v61.6,6.98
  Bottom 0.152: v45.45,13.69 45.29,13.69 44.68,13.08 44.68,10.11 47.2,7.59 60.99,7.59 v61.6,6.98
NLEDB\  (via drill 0.4)
  Top 0.152: IC2.23 46.12,21.37 44.53,19.78 44.53,13.15 44.91,12.77 v45.45,12.77 | R18.1 71.73,5.25 v71.73,6.98
  Bottom 0.152: v45.45,12.77 45.45,10.11 47.5,8.05 64.34,8.05 65.41,6.98 v71.73,6.98
NSHIELD  (via drill 0.4)
  Top 0.152: C22.2 77.55,10.09 C21.2
  Bottom 0.406: R33*.2 65.4,20.61 65.41,20.62 v66.93,20.62
  pour Ground (isolate 0.813): 64.8,22.83 97.19,22.83 97.19,7.59 64.8,7.59
  pour Bottom (isolate 0.813): 64.8,22.83 97.19,22.83 97.19,7.59 64.8,7.59
NXTAL1
  Top 0.152: IC2.127 45.83,10.26 45.37,9.8 45.37,9.19 | R16.2 46.82,9.19 45.37,9.19 | 45.37,9.19 45.37,9.11 C17.1 45.3,7.75 42.63,5.08 39.35,5.08 39.32,5.05 Y3.P$2
NXTAL2
  Top 0.152: R16.1 48.49,9.19 48.49,9.34 | Y3.P$1 48.57,5.08 48.57,9.11 R16.1 | R16.1 48.56,9.18 48.57,9.19 48.58,9.18 C18.1 | IC2.128 46.23,10.46 46.51,10.18 48.04,10.18 48.49,9.72 48.49,9.42 48.51,9.41 R16.1
PB0
  Top 0.152: IC1.10 32.43,54.77 35.69,58.03 35.69,68.93 34.09,70.53 31.8,70.53 30.51,71.83 30.51,72.66 29.24,73.94 J5.47
PB1  (via drill 0.4)
  Top 0.152: J5.48 29.37,72.36 31.58,70.15 33.86,70.15 35.31,68.7 35.31,58.26 32.62,55.57 IC1.11 29.42,55.57 27.61,53.77 27.61,52.78 29.29,51.1 29.29,47.21 30.05,46.45 30.05,41.73 28.76,40.43 v25.94,40.43 | v24.64,29.99 24.03,29.99 IC13.2
  Bottom 0.152: v24.64,29.99 25.33,30.68 25.33,39.82 v25.94,40.43
PB2  (via drill 0.4)
  Top 0.152: J5.49 26.7,74.04 28.07,72.66 28.07,71.9 28.83,71.14 29.98,71.14 31.35,69.77 33.63,69.77 34.93,68.47 34.93,58.49 32.81,56.37 IC1.12 29.54,56.37 27.16,54 27.16,52.47 28.53,51.1 v28.53,47.14 | v24.64,31.29 24.03,31.29 IC13.1
  Bottom 0.152: v28.53,47.14 28.07,46.68 28.07,43.94 24.87,40.74 24.87,31.52 v24.64,31.29
PB3  (via drill 0.4)
  Top 0.152: J5.50 26.93,72.36 28.53,70.76 29.75,70.76 31.12,69.39 33.41,69.39 34.55,68.25 34.55,58.72 33,57.17 IC1.13 29.57,57.17 26.7,54.3 26.7,49.58 27.61,48.66 v27.61,47.67 | IC12.4 23.2,34.34 v22.2,34.34
  Bottom 0.152: v27.61,47.67 27.61,44.17 24.41,40.97 24.41,37.31 22.2,35.1 v22.2,34.34
PB4  (via drill 0.4)
  Top 0.152: J5.51 24.16,74.14 25.48,72.82 25.48,71.9 26.24,71.14 27.39,71.14 28.22,70.3 29.52,70.3 30.82,69.01 33.18,69.01 34.17,68.02 34.17,58.95 33.19,57.97 IC1.14 29.69,57.97 26.24,54.53 26.24,48.89 v26.78,48.28 | R7.2 32.03,33.27 32.03,34.03 29.9,36.16 IC11.1 | 29.89,37.16 IC11.1 | 29.89,37.16 29.89,37.62 v29.75,37.77 | IC11.1 | 29.89,37.16 29.9,37.16 | IC11.2 29.24,37.16 29.89,37.16
  Bottom 0.152: v29.75,37.77 29.9,37.92 29.9,47.44 28.76,48.59 27.08,48.59 v26.78,48.28
PB5
  Top 0.152: IC1.15 33.38,58.77 33.79,59.18 33.79,67.79 32.95,68.63 30.51,68.63 29.21,69.92 27.92,69.92 27.16,70.68 26.01,70.68 24.34,72.36 J5.52
PB6  (via drill 0.4)
  Top 0.152: 31.23,59.67 IC1.16 | 31.23,59.67 31.13,59.57 | 31.23,59.67 31.12,59.56 v30.21,60.47
  Bottom 0.152: J5.53 21.6,74.19 21.6,73.96 22.89,72.66 22.89,71.67 23.58,70.99 27.16,70.99 31.12,67.03 31.12,62.68 30.21,61.77 v30.21,60.47
PB7  (via drill 0.4)
  Top 0.152: IC1.17 29.23,60.03 v29.21,59.86
  Bottom 0.152: J5.54 21.62,72.03 21.85,72.03 23.35,70.53 26.93,70.53 30.66,66.8 30.66,62.99 29.21,61.54 v29.21,59.86
PD0  (via drill 0.4)
  Top 0.152: IC1.25 v22.83,59.19 | IC1.25
  Bottom 0.152: J5.55 19.08,74.04 20.15,72.97 20.15,71.83 14.66,66.34 14.66,64.89 15.42,64.13 18.85,64.13 22.81,60.17 22.81,59.71 22.83,59.7 v22.83,59.19
PD1  (via drill 0.4)
  Top 0.152: IC1.26 22.03,61.67 v22.03,59.89
  Bottom 0.152: J5.56 19.08,71.45 14.2,66.57 14.2,64.66 15.19,63.67 18.32,63.67 22.02,59.97 v22.03,59.89
PD2  (via drill 0.4)
  Top 0.152: IC1.27 v21.23,59.19 | IC1.27 | v63.89,76.17 63.73,76.02 63.73,71.6 64.8,70.53 64.8,64.97 65.8,63.97 JP1.9
  Bottom 0.152: 17.75,73.69 17.79,73.66 17.79,70.84 13.75,66.8 13.75,64.44 14.96,63.22 18.09,63.22 21.21,60.09 21.21,59.13 v21.23,59.19 | 17.75,73.69 17.79,73.73 | 17.75,73.69 J5.57 16.54,75.76 17.4,76.63 63.43,76.63 v63.89,76.17
PD3  (via drill 0.4)
  Top 0.152: IC1.28 v20.43,59.89 | IC1.28
  Bottom 0.152: v20.43,59.89 20.43,60.11 17.79,62.76 14.74,62.76 13.29,64.21 13.29,67.03 16.49,70.23 16.49,72.28 16.57,72.36 J5.58 16.54,73.07 15.19,74.42 15.19,76.09 16.18,77.08 72.19,77.08 73.72,75.56 73.72,70 67.77,64.05 67.77,59.9 JP1.3
PD4  (via drill 0.4)
  Top 0.152: IC1.29 | IC1.29 | v19.63,59.27 IC1.29 | J5.59 14.05,74.85 14.05,74.8 15.27,73.58 15.27,71.29 14.66,70.68 7.12,70.68 6.05,69.62 3.31,69.62 2.16,68.47 2.16,24.28 3.61,22.83 20.68,22.83 21.75,23.9 25.14,23.9 JP2.6
  Bottom 0.152: J5.59 15.27,73.63 15.27,69.69 12.83,67.25 12.83,63.98 14.51,62.3 17.56,62.3 19.61,60.24 19.61,59.79 19.63,59.77 v19.63,59.27
PD5  (via drill 0.4)
  Top 0.152: IC1.30 18.85,61.55 v18.85,59.94 | IC1.30 | J5.60 14,72 13.14,71.14 6.89,71.14 5.82,70.07 3.08,70.07 1.71,68.7 1.71,24.05 3.38,22.37 20.68,22.37 22.16,20.89 JP2.1
  Bottom 0.152: J5.60 13.97,72.33 13.97,69.08 12.37,67.48 12.37,63.75 14.28,61.84 17.25,61.84 18.85,60.24 v18.85,59.94
PD6  (via drill 0.4)
  Top 0.152: IC1.31 v18.03,59.27
  Bottom 0.152: J5.61 12.75,73.61 12.75,68.55 11.92,67.71 11.92,63.52 14.05,61.39 17.02,61.39 18.01,60.4 18.01,60.02 18.03,60 v18.03,59.27
PD7  (via drill 0.4)
  Top 0.152: IC1.32 v17.23,59.97
  Bottom 0.152: J5.62 11.46,63.29 14.74,60.02 17.18,60.02 v17.23,59.97
PE0  (via drill 0.4)
  Top 0.152: IC1.2 31.98,48.37 33.41,49.8 | 33.41,49.8 38.74,55.14 38.74,69.92 40.57,71.75 40.57,73.73 J5.39 | v61.14,52.7 59.31,52.7 56.27,49.65 56.27,45.92 57.03,45.16 57.03,44.47 55.81,43.25 55.81,41.96 53.98,40.13 53.98,33.19 52.91,32.13 36.23,32.13 34.17,34.18 34.17,36.55 30.82,39.9 30.82,40.97 35.01,45.16 35.01,48.2 33.41,49.8
  Bottom 0.152: v61.14,52.7 61.14,53.16 60.38,53.92 60.38,55.14 62.06,56.81 64.34,56.81 64.88,57.35 64.88,60.32 64.27,60.93 63.28,60.93 62.74,61.46 62.74,62.3 63.28,62.84 63.96,62.84 64.88,63.75 64.88,64.89 63.84,65.93 JP1.12
PE1
  Top 0.152: J5.40 38.36,71.32 38.36,55.52 32.01,49.17 IC1.3 30.03,49.17 29.75,48.89 29.75,47.29 30.51,46.53 30.51,41.35 30.36,41.19 30.36,39.67 33.71,36.32 33.71,33.88 35.92,31.67 53.14,31.67 54.44,32.96 54.44,39.9 56.27,41.73 56.27,43.02 57.48,44.24 57.48,45.38 56.72,46.15 56.72,49.42 59.24,51.94 61.37,51.94 63.8,54.37 JP1.2
PE2
  Top 0.152: IC1.4 31.98,49.97 37.98,55.98 37.98,72.82 36.86,73.94 J5.41 | J5.41 36.84,74.88 | J5.41 38.13,76.17 57.71,76.17 58.48,75.41 58.48,71.67 60.23,69.92 60.23,65.43 62.21,63.45 62.21,61.31 63.59,59.93 JP1.6
PE3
